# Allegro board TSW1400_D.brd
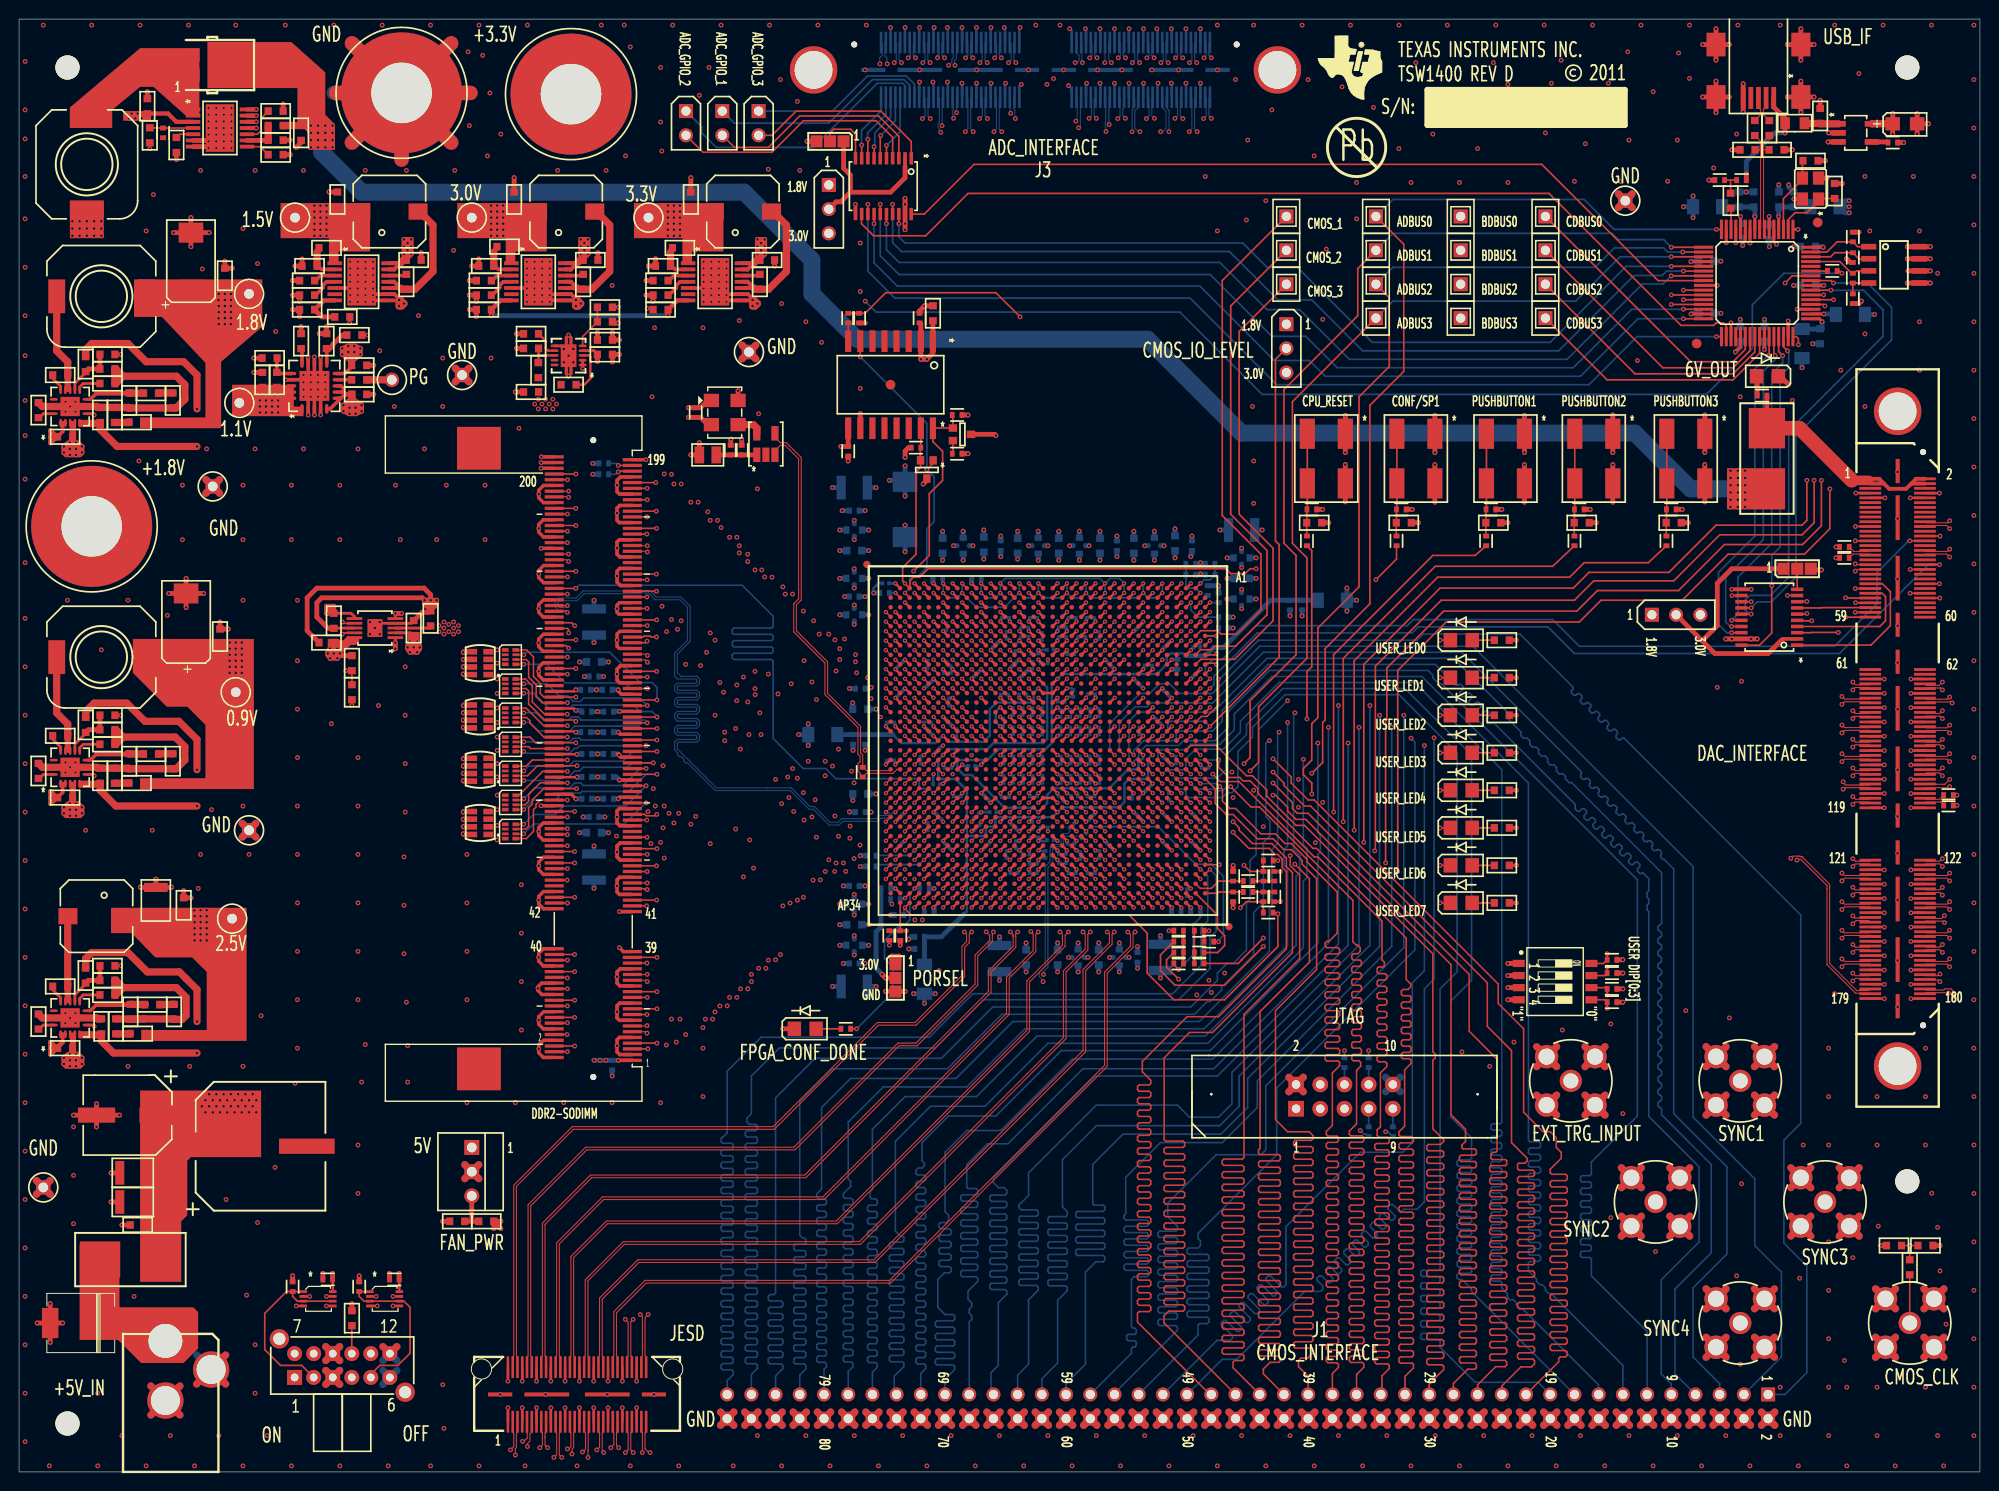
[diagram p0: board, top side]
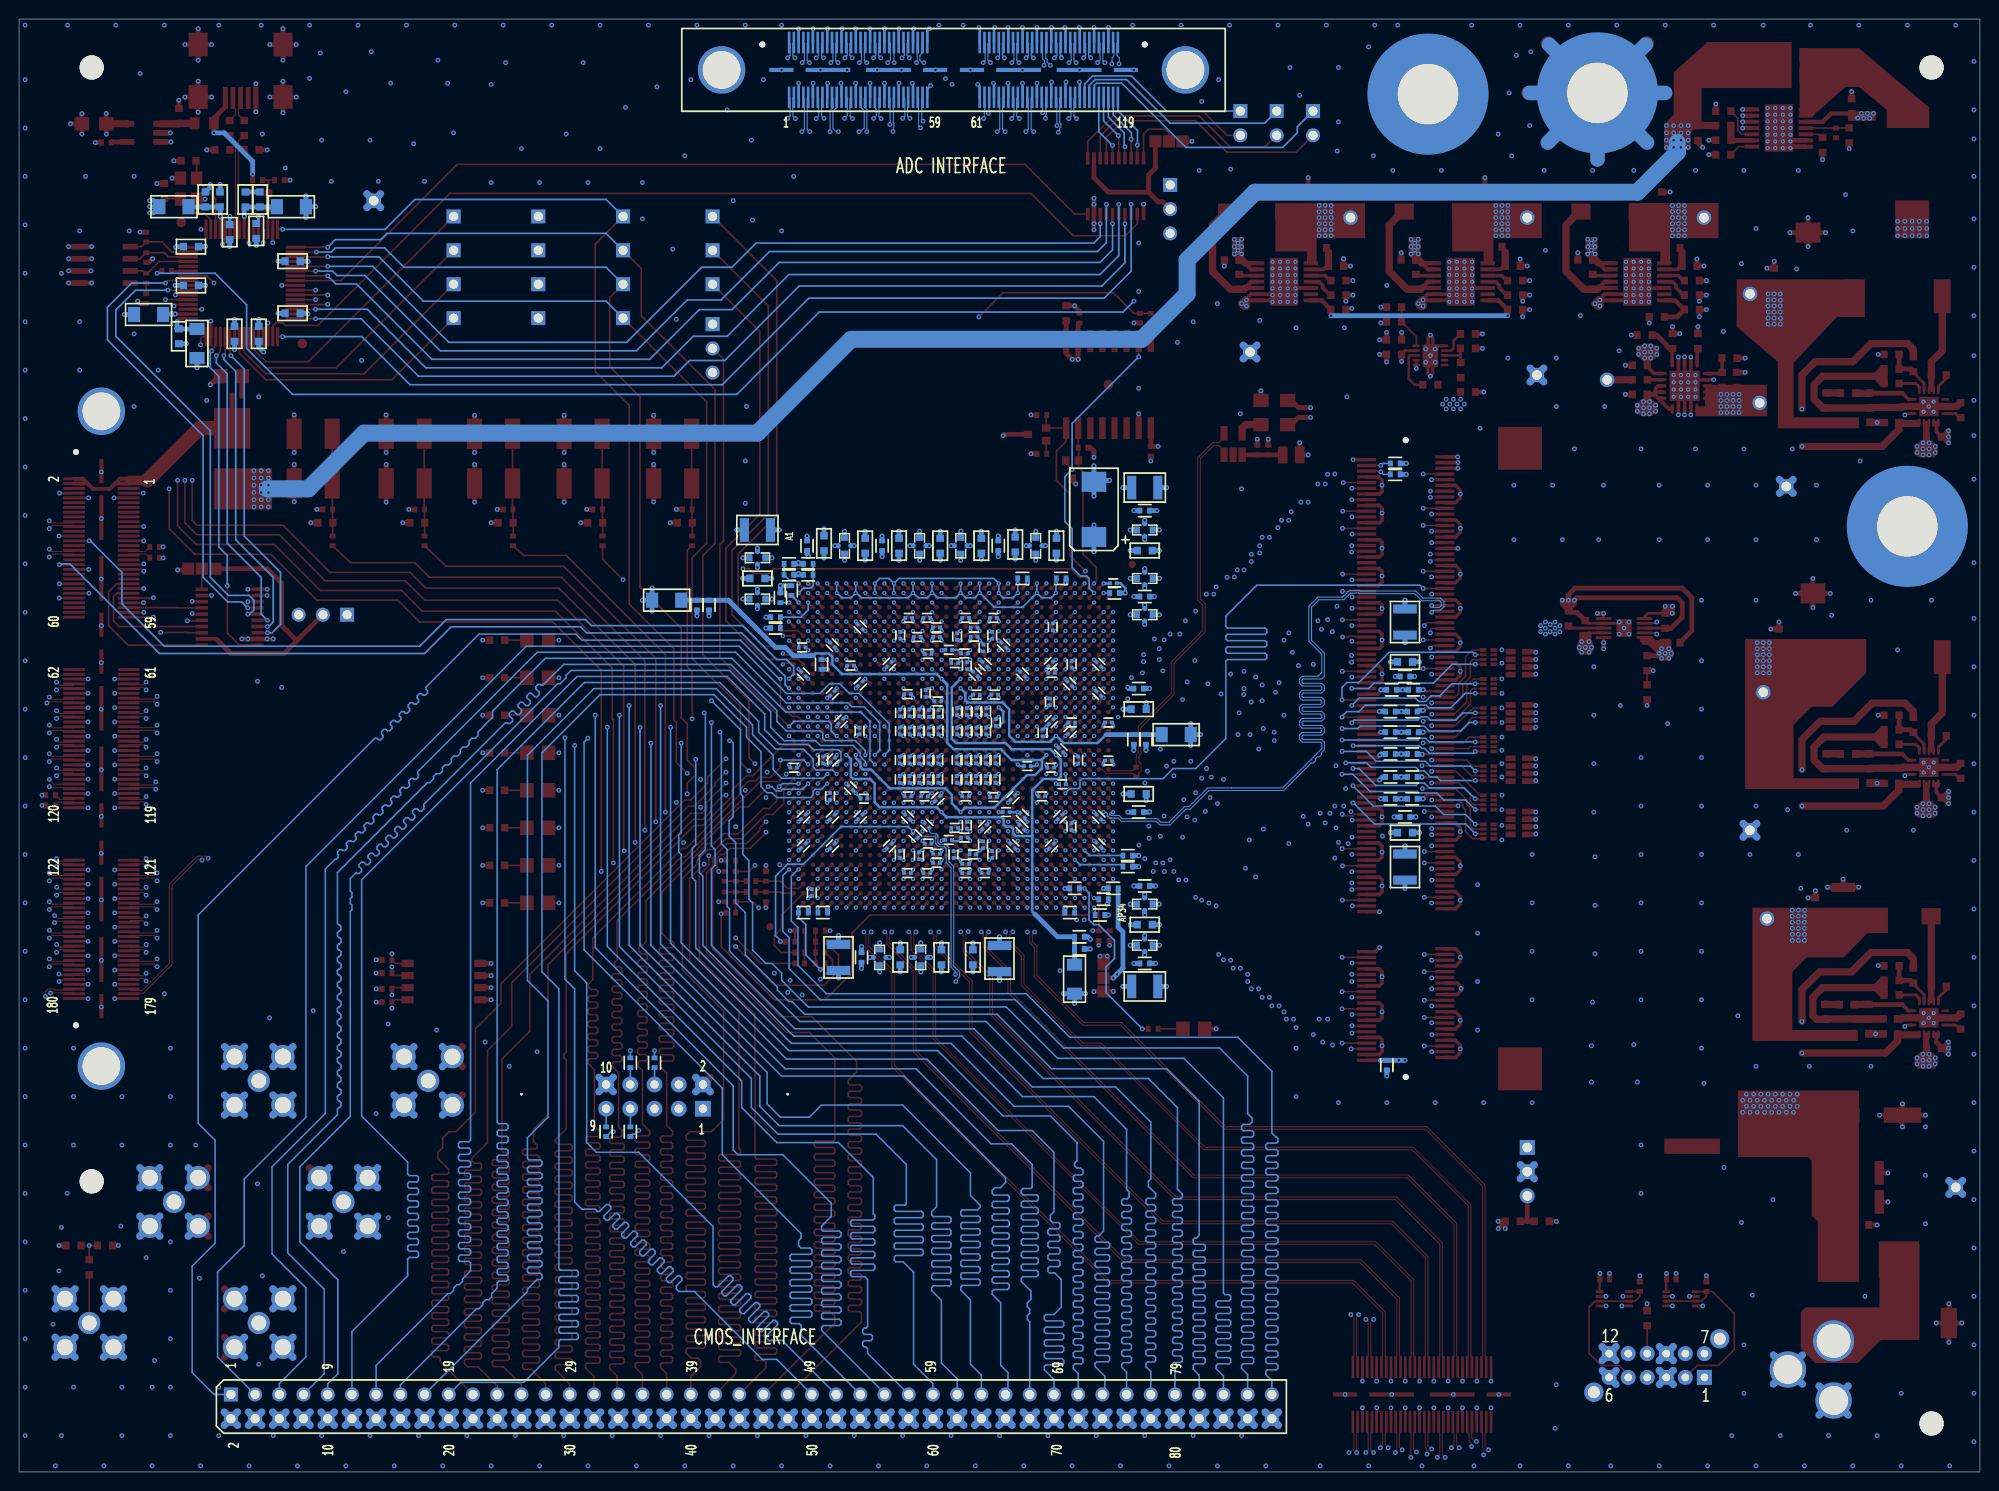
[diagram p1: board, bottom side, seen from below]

Outline 205.74 x 152.4 mm; copper layers: TOP, L2-GND1, L3-SIG1, L4-SIG2, L5-GND2, L6-PWR1, L7-PWR2, L8-GND3, L9-SIG3, L10-SIG4, L11-GND4, BOTTOM. Coordinates in mm from the lower left corner of the outline.
Outline path: 0,152.4 205.74,152.4 205.74,0 0,0 0,152.4

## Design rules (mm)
net group DIFFPAIR2: nets GXB_RX2M GXB_RX2P
net group DIFFPAIR11: nets GXB_TX2M GXB_TX2P
net group DIFFPAIR20: nets CLK_OSCN CLK_OSCP
net group DIFFPAIR26: nets DS5N DS5P
net group DIFFPAIR28: nets DS3N DS3P
net group DIFFPAIR31: nets DBCLKN DBCLKP
net group DIFFPAIR32: nets DA15N DA15P
net group DIFFPAIR33: nets DA14N DA14P
net group DIFFPAIR34: nets DA13N DA13P
net group DIFFPAIR35: nets DA12N DA12P
net group DIFFPAIR36: nets DA11N DA11P
net group DIFFPAIR37: nets DA10N DA10P
net group DIFFPAIR38: nets DA9N DA9P
net group DIFFPAIR39: nets DA8N DA8P
net group DIFFPAIR40: nets DACLKN DACLKP
net group DIFFPAIR41: nets FPGA_CLKN FPGA_CLKP
net group DIFFPAIR42: nets DB8N DB8P
net group DIFFPAIR43: nets DB9N DB9P
net group DIFFPAIR44: nets DB10N DB10P
net group DIFFPAIR45: nets DB11N DB11P
net group DIFFPAIR46: nets DB12N DB12P
net group DIFFPAIR47: nets DB13N DB13P
net group DIFFPAIR48: nets DB14N DB14P
net group DIFFPAIR49: nets DB15N DB15P
net group DIFFPAIR50: nets DA7N DA7P
net group DIFFPAIR51: nets DA6N DA6P
net group DIFFPAIR52: nets DA5N DA5P
net group DIFFPAIR53: nets DA4N DA4P
net group DIFFPAIR54: nets DA3N DA3P
net group DIFFPAIR55: nets DA2N DA2P
net group DIFFPAIR56: nets DA1N DA1P
net group DIFFPAIR57: nets DA0N DA0P
net group DIFFPAIR58: nets OSTROBE_N OSTROBE_P
net group DIFFPAIR59: nets SYNCA_N SYNCA_P
net group DIFFPAIR60: nets ISTROBE_N ISTROBE_P
net group DIFFPAIR61: nets PARITY_N PARITY_P
net group DIFFPAIR62: nets DB0N DB0P
net group DIFFPAIR63: nets DB1N DB1P
net group DIFFPAIR64: nets DB2N DB2P
net group DIFFPAIR65: nets DB3N DB3P
net group DIFFPAIR66: nets DB4N DB4P
net group DIFFPAIR67: nets DB5N DB5P
net group DIFFPAIR68: nets DB6N DB6P
net group DIFFPAIR69: nets DB7N DB7P
net group DIFFPAIR71: nets INPUT10_M INPUT10_P
net group DIFFPAIR88: nets INPUT0_M INPUT0_P
net group DIFFPAIR89: nets INPUT1_M INPUT1_P
net group DIFFPAIR109: nets DM DP
net group DIFFPAIR110: nets N27224376 N27224380
net group DIFFPAIR111: nets DDR2_DQS7 DDR2_DQSN7
net group DIFFPAIR112: nets DDR2_DQS6 DDR2_DQSN6
net group DIFFPAIR113: nets DDR2_DQS1 DDR2_DQSN1
net group DIFFPAIR114: nets DDR2_DQS4 DDR2_DQSN4
net group DIFFPAIR115: nets DDR2_DQS0 DDR2_DQSN0
net group DIFFPAIR116: nets DDR2_DQS3 DDR2_DQSN3
net group DIFFPAIR117: nets DDR2_DQS2 DDR2_DQSN2
net group DIFFPAIR118: nets DDR2_DQS5 DDR2_DQSN5
net group DIFFPAIR119: nets DDR2_CLK_N1 DDR2_CLK_P1
net group DIFFPAIR120: nets FPGA_CLK2_N FPGA_CLK2_P
net group DIFFPAIR141: nets FPGACLK2N FPGACLK2P
net group DIFFPAIR142: nets FPGACLKN FPGACLKP
net group 100 OHM: nets CLK_GXB1_M CLK_GXB1_P CLK_GXB2_M CLK_GXB2_P CLK_GXB3_M CLK_GXB3_P CLK_GXB4_M CLK_GXB4_P DCLK_M DCLK_P FCLK_M FCLK_P GXB_RX0M GXB_RX0P GXB_RX1M GXB_RX1P GXB_RX3M GXB_RX3P GXB_RX4P GXB_RX5M GXB_RX5P GXB_RX6M GXB_RX6P GXB_RX7P GXB_TX0M GXB_TX0P GXB_TX1M GXB_TX1P GXB_TX3M GXB_TX3P GXB_TX4P GXB_TX5M GXB_TX5P GXB_TX6M GXB_TX6P GXB_TX7P INPUT2_P INPUT3_P INPUT4_M INPUT4_P INPUT5_M INPUT5_P INPUT6_M INPUT6_P INPUT7_M INPUT7_P INPUT8_M INPUT8_P INPUT9_M INPUT9_P INPUT11_M INPUT11_P INPUT12_P INPUT13_M INPUT13_P INPUT14_M INPUT14_P INPUT15_P INPUT16_M INPUT16_P INPUT17_M INPUT17_P INPUT18_P INPUT19_M INPUT19_P INPUT20_P INPUT21_P INPUT22_M INPUT22_P INPUT23_P INPUT24_M INPUT24_P INPUT25_P INPUT26_M INPUT26_P INPUT27_P INPUT28_P INPUT29_P INPUT30_M INPUT30_P INPUT31_P INPUT32_M INPUT32_P INPUT33_P INPUT34_M INPUT34_P N28765297
net group DIFFPAIR4: nets GXB_RX4M
net group DIFFPAIR6: nets GXB_RX7M
net group DIFFPAIR13: nets GXB_TX4M
net group DIFFPAIR16: nets GXB_TX7M
net group DIFFPAIR73: nets INPUT12_M
net group DIFFPAIR76: nets INPUT15_M
net group DIFFPAIR79: nets INPUT18_M
net group DIFFPAIR80: nets INPUT28_M
net group DIFFPAIR81: nets INPUT29_M
net group DIFFPAIR83: nets INPUT31_M
net group DIFFPAIR85: nets INPUT33_M
net group DIFFPAIR90: nets INPUT2_M
net group DIFFPAIR91: nets INPUT3_M
net group DIFFPAIR99: nets INPUT20_M
net group DIFFPAIR100: nets INPUT21_M
net group DIFFPAIR102: nets INPUT23_M
net group DIFFPAIR104: nets INPUT25_M
net group DIFFPAIR106: nets INPUT27_M

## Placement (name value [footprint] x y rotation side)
C1  0.1uF  [0603]  181.99 133.48 90 bottom
C2  4.7uF  [0603]  180.47 133.48 90 bottom
C3  10uF  [0603]  188.98 119.13 270 bottom
C4  100uF  [1206]  187.07 118.36 270 bottom
C5  0.1uF  [0603]  186.18 133.48 90 bottom
C6  4.7uF  [0603]  184.66 133.48 90 bottom
C7  100uF  [1206]  192.15 121.41 0 bottom
C8  10uF  [0603]  188.98 142.24 90 top
C9  4.7uF  [TANT_A]  197.87 141.41 0 top
C10  0.01uF  [0402]  196.6 139.45 0 top
C11  22pF  [0603]  181.36 138.68 180 top
C12  22pF  [0603]  184.4 138.68 0 top
C13  0.1uF  [0603]  180.59 119.38 90 bottom
C14  0.1uF  [0603]  187.71 128.52 180 bottom
C15  0.1uF  [0603]  180.85 130.18 270 bottom
C16  0.1uF  [0603]  177.04 121.54 0 bottom
C17  0.1uF  [0603]  177.04 127 0 bottom
C18  0.1uF  [0603]  187.71 124.46 180 bottom
C19  0.1uF  [0603]  183.13 119.38 90 bottom
C20  27pF  [0603]  190.5 134.37 90 top
C21  27pF  [0603]  187.96 137.54 0 top
C22  0.1uF  [0402]  61.72 82.04 180 bottom
C23  0.1uF  [0402]  61.85 79.76 180 bottom
C24  0.1uF  [0402]  61.85 77.6 180 bottom
C25  0.1uF  [0402]  61.85 75.31 180 bottom
C26  0.1uF  [0402]  61.85 72.9 180 bottom
C27  0.1uF  [0402]  61.85 70.61 180 bottom
C28  0.1uF  [0402]  59.44 82.04 0 bottom
C29  0.1uF  [0402]  59.44 77.6 0 bottom
C30  0.1uF  [0402]  59.56 79.76 0 bottom
C31  0.1uF  [0402]  59.56 75.31 0 bottom
C32  0.1uF  [0402]  59.56 72.9 0 bottom
C33  0.1uF  [0402]  59.56 70.61 0 bottom
C34  0.1uF  [0402]  62.23 42.67 270 bottom
C35  100uF  [1210]  60.33 63.45 270 bottom
C36  4.7uF  [0603]  60.33 67.06 0 bottom
C37  2.2uF  [0603]  60.33 84.96 180 bottom
C38  1uF  [0402]  60.33 68.71 0 bottom
C39  0.47uF  [0402]  60.33 83.44 180 bottom
C40  1uF  [0402]  75.82 107.19 90 top
C41  0.1uF  [0402]  74.68 107.19 90 top
C45  0.1uF  [0402]  70.99 111.12 270 top
C46  0.1uF  [0603]  198.37 21.46 90 top
C47  1uF  [0603]  25.53 114.55 270 top
C48  1uF  [0603]  35.69 113.03 180 top
C49  0.1uF  [0603]  29.59 118.62 270 top
C50  1uF  [0603]  35.69 116.08 180 top
C51  0.1uF  [0603]  4.32 77.22 0 top
C52  10uF  [0603]  41.4 127.13 0 top
C53  0.1uF  [0603]  21.08 87.63 270 top
C54  470uF  [TANT_E]  17.53 89.15 90 top
C55  10uF  [0603]  4.83 70.74 180 top
C56  10uF  [0603]  8.51 73.03 90 top
C57  330pF  [0603]  11.56 74.55 270 top
C58  0.018uF  [0603]  9.27 76.33 0 top
C59  0.1uF  [0603]  40.64 124.84 90 top
C60  1uF  [0603]  30.23 124.97 0 top
C61  0.1uF  [0603]  30.23 123.44 0 top
C62  22uF  [0603]  33.4 133.48 90 top
C63  1500pF  [0603]  16.13 74.55 270 top
C64  0.1uF  [0603]  4.32 115.06 0 top
C65  0.1uF  [0603]  21.59 125.48 270 top
C66  470uF  [TANT_E]  18.03 127 90 top
C67  10uF  [0603]  4.83 108.58 180 top
C68  10uF  [0603]  8.51 110.87 90 top
C69  330pF  [0603]  11.56 112.39 270 top
C70  0.018uF  [0603]  9.27 114.17 0 top
C71  22uF  [0603]  43.18 89.53 90 top
C72  22uF  [0603]  41.4 88.52 90 top
C73  4.7uF  [0603]  32.26 87 180 top
C74  1500pF  [0603]  16.13 112.39 270 top
C75  0.1uF  [0603]  33.02 89.28 90 top
C76  1uF  [0603]  12.45 25.91 0 top
C77  47uF  [CAP_SMD_8MM]  11.23 37.43 270 top
C78  680uF  [CAP_SMD_12_5MM]  25.34 34.16 90 top
C79  10uF  [0603]  78.49 127.13 0 top
C80  10uF  [1210]  11.94 28.32 180 top
C81  10uF  [1210]  11.94 31.37 180 top
C82  0.1uF  [0603]  77.72 124.84 90 top
C83  1uF  [0603]  67.31 124.97 0 top
C84  0.1uF  [0603]  67.31 123.44 0 top
C85  22uF  [0603]  70.48 133.48 90 top
C86  0.1uF  [0603]  4.32 50.93 0 top
C87  0.1uF  [0603]  17.27 59.44 270 top
C88  100uF  [1210]  14.35 59.94 90 top
C90  1200pF  [0603]  11.68 48.26 270 top
C91  0.018uF  [0603]  9.27 50.04 0 top
C92  22uF  [0603]  4.83 44.45 180 top
C93  .022uF  [0603]  16.26 48.26 270 top
C94  2.2uF  [0603]  95.89 121.54 90 top
C95  0.1uF  [0402]  94.49 121.03 90 top
C96  10uF  [0603]  59.94 127.13 0 top
C97  0.1uF  [0603]  59.18 124.84 90 top
C98  1uF  [0603]  48.77 124.97 0 top
C99  0.1uF  [0603]  48.77 123.44 0 top
C100  22uF  [0603]  51.94 133.48 90 top
C101  22uF  [1210]  102.87 53.85 270 bottom
C102  10uF  [0603]  105.66 53.98 270 bottom
C103  0.1uF  [0201]  111.33 64.64 90 bottom
C104  0.1uF  [0201]  106.43 62.81 180 bottom
C105  0.1uF  [0201]  104.39 62.81 180 bottom
C106  0.1uF  [0201]  112.52 62.81 0 bottom
C107  0.1uF  [0201]  110.49 62.81 0 bottom
C108  0.1uF  [0201]  107.7 64.77 90 bottom
C109  4.7uF  [0603]  109.09 97.16 270 bottom
C110  0.1uF  [0201]  109.47 63.88 0 bottom
C111  0.1uF  [0201]  106.43 63.78 180 bottom
C112  0.1uF  [0201]  105.54 88.57 0 bottom
C113  0.1uF  [0201]  109.47 88.6 0 bottom
C114  22uF  [1210]  60.33 89.15 90 bottom
C115  0.47uF  [0402]  88.27 69.22 180 bottom
C116  0.47uF  [0402]  88.27 82.17 180 bottom
C117  10uF  [0603]  88.27 71.12 180 bottom
C118  0.1uF  [0201]  92.46 65.79 45 bottom
C119  0.1uF  [0201]  91.44 74.63 180 bottom
C120  0.1uF  [0201]  96.52 68.71 135 bottom
C121  0.1uF  [0201]  96.27 72.14 0 bottom
C122  0.1uF  [0201]  94.61 74.68 90 bottom
C123  0.1uF  [0201]  92.46 68.71 45 bottom
C124  10uF  [0603]  108.97 53.98 270 bottom
C125  0.1uF  [0201]  120.4 65.66 135 bottom
C126  0.1uF  [0201]  103.5 70.79 180 bottom
C127  0.1uF  [0201]  110.74 70.87 180 bottom
C128  0.1uF  [0201]  113.31 79.63 270 bottom
C129  0.1uF  [0201]  118.49 84.58 0 bottom
C130  0.1uF  [0201]  106.43 70.87 0 bottom
C131  0.1uF  [0201]  95.3 84.71 90 bottom
C132  0.1uF  [0201]  120.4 86.74 225 bottom
C133  0.1uF  [0201]  103.25 78.61 270 bottom
C134  2.2uF  [0603]  88.27 80.01 180 bottom
C135  0.1uF  [0201]  109.35 70.64 315 bottom
C136  0.1uF  [0201]  119.51 78.74 135 bottom
C137  0.1uF  [0201]  118.49 71.75 45 bottom
C138  0.1uF  [0201]  120.4 81.66 135 bottom
C139  10uF  [0603]  104.78 97.16 90 bottom
C140  0.1uF  [0201]  123.44 83.69 225 bottom
C141  0.1uF  [0201]  112.47 70.87 180 bottom
C143  0.1uF  [0201]  102.18 69.22 0 bottom
C144  330uF  [TANT_D]  92.96 100.97 90 bottom
C145  100uF  [1210]  87.63 103.25 180 bottom
C146  100uF  [1210]  128.27 98.81 0 bottom
C147  100uF  [1210]  87.63 50.93 180 bottom
C148  100uF  [1210]  119.76 53.98 270 bottom
C149  10uF  [0603]  87.63 96.65 180 bottom
C150  10uF  [0603]  87.63 57.4 180 bottom
C151  10uF  [0603]  96.9 97.16 90 bottom
C152  10uF  [0603]  101.22 97.28 90 bottom
C153  10uF  [0603]  113.41 97.16 90 bottom
C154  10uF  [0603]  116.97 97.16 90 bottom
C155  10uF  [0603]  121.28 97.41 90 bottom
C156  2.2uF  [0603]  113.28 53.98 270 bottom
C157  0.1uF  [0201]  120.37 74.68 135 bottom
C158  0.1uF  [0201]  104.27 77.72 270 bottom
C159  0.1uF  [0201]  111.3 79.63 270 bottom
C160  0.1uF  [0201]  106.3 84.58 90 bottom
C161  0.1uF  [0201]  106.3 77.72 270 bottom
C162  0.1uF  [0201]  122.56 60.76 90 bottom
C163  10uF  [0603]  128.27 93.73 0 bottom
C164  0.1uF  [0201]  105.28 79.76 90 bottom
C165  0.1uF  [0201]  106.55 66.55 180 bottom
C166  0.1uF  [C-0603_X2Y]  87.63 59.56 0 bottom
C167  0.1uF  [C-0603_X2Y]  87.63 55.24 0 bottom
C168  0.1uF  [C-0603_X2Y]  87.63 98.81 180 bottom
C169  0.1uF  [C-0603_X2Y]  115.44 53.98 270 bottom
C170  0.1uF  [C-0603_X2Y]  106.93 97.16 270 bottom
C171  0.22uF  [C-0603_X2Y]  111.25 97.16 270 bottom
C172  0.22uF  [C-0603_X2Y]  128.27 91.57 180 bottom
C173  10nF  [C-0603_X2Y]  87.63 93.73 180 bottom
C174  10nF  [C-0603_X2Y]  128.27 95.89 0 bottom
C175  10nF  [C-0603_X2Y]  99.06 97.16 270 bottom
C176  10nF  [C-0603_X2Y]  119.13 97.16 90 bottom
C177  10nF  [C-0603_X2Y]  111.12 53.98 90 bottom
C178  10nF  [C-0603_X2Y]  87.63 89.92 180 bottom
C179  22nF  [0201]  104.32 72.64 90 bottom
C180  22nF  [0201]  104.27 79.76 90 bottom
C181  22nF  [0201]  109.3 72.64 90 bottom
C182  22nF  [0201]  99.95 74.04 0 bottom
C183  22nF  [0201]  111.3 77.72 90 bottom
C184  22nF  [0201]  95.3 78.61 180 bottom
C185  22nF  [0201]  112.29 77.72 270 bottom
C186  0.1uF  [0201]  123.44 65.68 135 bottom
C187  22nF  [0201]  111.3 72.64 90 bottom
C188  22nF  [0201]  107.37 74.68 270 bottom
C189  0.1uF  [0201]  90.93 93.22 180 bottom
C190  22nF  [0201]  108.2 86.23 180 bottom
C191  22nF  [0201]  100.46 68.86 45 bottom
C192  22nF  [0201]  111.3 74.68 90 bottom
C193  22nF  [0201]  105.28 77.72 270 bottom
C194  22nF  [0201]  105.33 74.68 270 bottom
C195  22nF  [0201]  112.32 72.64 270 bottom
C196  22nF  [0201]  110.31 74.68 270 bottom
C197  0.47uF  [0402]  87.63 100.84 180 bottom
C198  0.47uF  [0402]  87.63 91.82 180 bottom
C199  1uF  [0402]  87.63 61.47 180 bottom
C200  1uF  [0402]  87.63 53.34 180 bottom
C201  1uF  [0402]  103 97.16 90 bottom
C202  1uF  [0402]  115.19 97.16 90 bottom
C203  1uF  [0402]  117.35 53.98 270 bottom
C204  1uF  [0402]  123.06 97.16 90 bottom
C205  22nF  [0201]  110.29 77.72 270 bottom
C206  22nF  [0201]  112.32 74.68 270 bottom
C207  22nF  [0201]  108.2 66.29 180 bottom
C208  22nF  [0201]  110.29 79.55 270 bottom
C209  22nF  [0201]  107.37 72.64 270 bottom
C210  22nF  [0201]  106.35 72.64 90 bottom
C211  22nF  [0201]  104.6 65.79 270 bottom
C212  22nF  [0201]  97.49 73.86 0 bottom
C213  22nF  [0201]  106.35 74.68 90 bottom
C214  22nF  [0201]  107.57 84.84 0 bottom
C215  22nF  [0201]  106.3 79.76 90 bottom
C216  22nF  [0201]  105.33 72.64 270 bottom
C217  22nF  [0201]  106.3 67.82 90 bottom
C218  0.1uF  [0201]  97.41 83.82 180 bottom
C219  22nF  [0201]  97.59 80.77 90 bottom
C220  22nF  [0201]  104.32 74.68 90 bottom
C221  22nF  [0201]  112.32 79.63 270 bottom
C222  22nF  [0201]  107.57 67.56 0 bottom
C223  22nF  [0201]  106.55 85.85 0 bottom
C224  0.1uF  [0201]  95.33 67.69 270 bottom
C225  22nF  [0201]  107.31 77.72 270 bottom
C226  22nF  [0201]  107.31 79.76 270 bottom
C227  0.1uF  [0402]  87 107.06 270 top
C228  22nF  [0201]  104.55 86.44 90 bottom
C229  22nF  [0201]  104.39 84.71 225 bottom
C230  22nF  [0201]  110.36 65.91 0 bottom
C231  22nF  [0201]  109.3 74.68 90 bottom
C232  22nF  [0201]  104.42 67.67 135 bottom
C233  0.1uF  [0201]  109.47 64.85 0 bottom
C234  0.1uF  [0201]  105.66 64.77 0 bottom
C235  0.1uF  [0201]  105.54 87.6 0 bottom
C236  0.1uF  [0201]  107.31 87.63 270 bottom
C237  0.1uF  [0201]  106.43 89.59 180 bottom
C238  0.1uF  [0201]  103.5 89.59 0 bottom
C239  0.1uF  [0201]  111.51 87.58 180 bottom
C240  0.1uF  [0201]  109.47 87.58 0 bottom
C241  0.1uF  [0201]  112.39 89.59 0 bottom
C242  0.1uF  [0201]  110.49 89.59 0 bottom
C243  0.1uF  [0201]  117.09 70.61 180 bottom
C244  0.1uF  [0201]  103.3 72.64 90 bottom
C245  0.1uF  [0201]  97.28 88.65 270 bottom
C246  0.1uF  [0201]  103.3 74.68 90 bottom
C247  0.1uF  [0201]  98.42 70.87 0 bottom
C248  0.1uF  [0201]  117.55 77.72 270 bottom
C249  0.1uF  [0201]  112.52 81.58 0 bottom
C250  0.1uF  [0201]  113.31 77.72 270 bottom
C251  0.1uF  [0201]  123.44 68.71 135 bottom
C252  0.1uF  [0201]  120.4 68.71 135 bottom
C253  0.1uF  [0201]  113.33 74.68 270 bottom
C254  0.1uF  [0201]  113.33 72.64 270 bottom
C255  0.1uF  [0201]  121.36 74.68 90 bottom
C257  0.1uF  [0201]  120.65 70.87 270 bottom
C258  0.1uF  [0201]  123.57 86.49 180 bottom
C259  0.1uF  [0201]  124.46 73.86 0 bottom
C260  22nF  [0201]  110.36 85.8 0 bottom
C261  22nF  [0201]  109.27 79.55 90 bottom
C262  22nF  [0201]  109.27 77.72 90 bottom
C263  22nF  [0201]  110.31 72.64 270 bottom
C264  0.1uF  [0402]  202.44 69.91 180 top
C265  0.1uF  [0201]  97.41 65.66 135 bottom
C266  0.1uF  [0201]  100.51 67.61 225 bottom
C267  0.1uF  [0201]  101.47 70.74 315 bottom
C268  0.1uF  [0201]  97.43 78.71 135 bottom
C269  0.1uF  [0201]  95.45 77.67 315 bottom
C270  0.1uF  [0201]  95.5 82.68 45 bottom
C271  0.1uF  [0201]  91.44 78.61 180 bottom
C272  0.1uF  [0201]  92.46 81.66 45 bottom
C273  0.1uF  [0201]  92.46 84.71 45 bottom
C274  0.1uF  [0201]  97.49 84.76 135 bottom
C275  0.1uF  [0201]  100.46 83.69 225 bottom
C276  0.1uF  [0201]  102.44 86.74 225 bottom
C277  0.1uF  [0201]  117.47 88.65 225 bottom
C278  0.1uF  [0201]  109.35 80.82 180 bottom
C279  0.1uF  [0201]  114.43 84.71 135 bottom
C280  0.1uF  [0201]  117.48 82.68 135 bottom
C281  0.1uF  [0201]  114.43 65.66 135 bottom
C282  0.1uF  [0201]  105.41 83.69 225 bottom
C283  0.1uF  [0201]  103.38 81.53 0 bottom
C284  0.1uF  [0201]  110.62 81.66 90 bottom
C285  0.1uF  [0201]  101.47 65.66 45 bottom
C286  0.1uF  [0201]  105.28 81.53 0 bottom
C287  0.1uF  [0201]  112.52 68.71 45 bottom
C288  0.1uF  [0201]  98.35 77.52 270 bottom
C289  0.1uF  [0201]  117.47 68.71 135 bottom
C290  0.1uF  [0201]  96.42 75.72 225 bottom
C291  0.1uF  [0402]  202.44 70.99 180 top
C292  0.1uF  [0402]  191.52 97.03 0 top
C293  0.1uF  [0402]  191.52 95.89 0 top
C294  1uF  [0603]  13.46 143.26 270 top
C295  10uF  [0603]  16.51 139.19 270 top
C296  .027uF  [0603]  29.59 140.46 270 top
C328  2.2uF  [0402]  87.5 76.83 270 bottom
C329  2.2uF  [0402]  134.62 90.93 270 bottom
C330  2.2uF  [0402]  94.49 54.86 180 bottom
C331  22uF  [0402]  88.77 76.83 270 bottom
C332  22uF  [0402]  133.35 90.93 270 bottom
C333  22uF  [0402]  94.49 56.13 180 bottom
C334  1uF  [0603]  61.47 118.75 180 top
C335  1uF  [0603]  61.47 117.22 180 top
C336  10uF  [0603]  53.72 113.28 180 top
C337  270pF  [0603]  53.72 119.38 180 top
C338  0.1uF  [0603]  145.29 99.57 0 top
C339  0.1uF  [0603]  154.69 99.57 0 top
C340  0.1uF  [0603]  163.96 99.57 0 top
C341  0.1uF  [0603]  173.61 99.57 0 top
C342  0.1uF  [0603]  135.89 99.57 0 top
C349  0.1uF  [0402]  39.37 20.19 180 top
C350  0.1uF  [0402]  32.38 20.19 180 top
C351  10pF  [0402]  94.11 107.44 180 top
C352  10pF  [0402]  98.42 106.81 0 top
C353  10pF  [0402]  98.42 110.87 0 top
C354  10pF  [0402]  88.14 121.03 270 top
C355  4.7pF  [0603]  8.64 46.74 90 top
CN1  0.1uF x4  [CA-AVE-0603-8]  48.39 84.84 90 top
CN4  0.1uF x4  [CA-AVE-0603-8]  48.39 79.25 90 top
CN7  0.1uF x4  [CA-AVE-0603-8]  48.39 73.66 90 top
CN10  0.1uF x4  [CA-AVE-0603-8]  48.39 68.07 90 top
D1  GREEN  [LED_0805]  82.49 46.48 180 top
D2  GREEN  [LED_0805]  151.32 87.25 180 top
D3  GREEN  [LED_0805]  151.32 83.31 180 top
D4  GREEN  [LED_0805]  151.32 79.38 180 top
D5  GREEN  [LED_0805]  151.32 75.44 180 top
D6  GREEN  [LED_0805]  151.32 71.5 180 top
D7  GREEN  [LED_0805]  151.32 67.56 180 top
D8  GREEN  [LED_0805]  151.32 63.63 180 top
D9  GREEN  [LED_0805]  151.32 59.69 180 top
D10  LED GREEN  [LED_0805]  183.45 114.94 0 top
D11  SS3P6L, 3A, 60V  [DIODE_SM_SS3P6L]  22.12 147.57 180 top
D14  B540C-13-F  [DO-214AB_RECTRON]  6.48 15.62 180 top
DN1  BAT54CW  [SOT_323]  95.25 105.16 180 top
DN2  BAT54CW  [SOT_323]  98.93 108.84 270 top
F1  4 AMP FUSE  [FUSE_SM_NANO]  11.68 22.28 0 top
F2  2 AMP FUSE  [FUSE_SM_NANO]  183.39 106.3 90 top
FB1  68 OHM @ 100MHz  [1206]  177.16 132.72 0 bottom
FB2  68 OHM @ 100MHz  [1206]  189.48 132.72 180 bottom
FB4  68 ohm @ 100MHz  [1206]  95 51.69 90 bottom
FB5  68 ohm @ 100MHz  [1206]  137.79 91.44 180 bottom
FB6  68 ohm @ 100MHz  [1206]  84.33 77.34 0 bottom
J1  SSQ-144-01-G-D  [HDR_THVT_2X44_100_F]  183.51 8.13 90 bottom
J2  QSH-030-01-L-D-A  [CON_SMVT_60POS_QSH_SAMTEC]  58.55 8.13 0 top
J3  QSH-060-01-L-D-A-RT1  [CON_SMVT_120POS_QSH_SAMTEC_RT1]  107.7 147.07 180 bottom
J4  QSH-090-01-L-D-A-RT1  [CON_SMVT_180POS_QSH_SAMTEC_RT1]  199.77 107.02 270 top
J5  USB_MINI_AB_MNE20-5G5P10  [CON_SMRT_USBMNE20_F]  182.5 147.57 270 top
J6  -  [SOCKET-SO-DIMM200]  60.25 74.83 90 top
J7  SMB_THVT_REC  [SMA_THVT_312X312]  198.37 15.62 180 top
J8  BANANA_JACK_RED  [CON_THVT_BANANA_JACK_250DIA]  7.62 99.19 0 top
J9  BANANA_JACK_BLK  [CON_THVT_BANANA_JACK_250DIA]  40.13 144.65 0 top
J10  BANANA_JACK_RED  [CON_THVT_BANANA_JACK_250DIA]  57.91 144.53 0 top
J11  SMB_THVT_REC  [SMA_THVT_312X312]  162.81 41.02 0 top
J12  CONN JACK PWR  [CON_THRT_POWERJACK_RAPC722]  15.35 10.62 0 top
J13  102153-1  [CON_THVT_2X5_100_M]  133.99 38.1 90 top
J14  SMB_THVT_REC  [SMA_THVT_312X312]  180.59 41.02 0 top
J15  SMB_THVT_REC  [SMA_THVT_312X312]  171.7 28.32 0 top
J16  SMB_THVT_REC  [SMA_THVT_312X312]  189.48 28.32 0 top
J17  SMB_THVT_REC  [SMA_THVT_312X312]  180.59 15.62 0 top
J18  22-11-2032  [HDR_THVT_1X3_100_M_KEYED]  47.5 34.04 0 top
JP3  HEADER_1x3_100_430L  [HDR_THVT_1X3_100_M]  84.96 135 0 top
JP4  HEADER_1x3_100_430L  [HDR_THVT_1X3_100_M]  171.32 89.92 90 top
JP5  JUMPER_1X2_100  [HDR_THVT_1X2_100_M]  77.6 142.75 0 top
JP6  JUMPER_1X2_100  [HDR_THVT_1X2_100_M]  73.79 142.75 0 top
JP7  JUMPER_1X2_100  [HDR_THVT_1X2_100_M]  69.98 142.75 0 top
JP8  HEADER_1x3_100_430L  [HDR_THVT_1X3_100_M]  132.97 120.4 0 top
L3  1K  @ 100MHZ  [0805]  186.31 141.48 0 top
L4  1.5A/330  [IND_0805]  72.26 106.68 0 top
L6  1.5uH  [IND_SM_MSS1048]  8.64 85.47 0 top
L7  2.2uH  [IND_SM_7447789002]  38.86 132.21 90 top
L8  1.5uH  [IND_SM_MSS1048]  8.64 123.32 0 top
L9  2.2uH  [IND_SM_7447789002]  75.95 132.21 90 top
L10  2.2uH  [IND_SM_7447789002]  8.13 58.29 270 top
L11  2.2uH  [IND_SM_7447789002]  57.4 132.21 90 top
L12  10uH  [IND_SM_MSS1048]  7.11 137.16 90 top
NOREF  -  [unnamed]  198.12 30.48 0 top
NOREF#2  -  [unnamed]  5.08 5.08 0 top
NOREF#3  -  [#2]  203.2 0 90 top
NOREF#4  -  [unnamed]  198.12 147.32 0 top
NOREF#5  -  [#2]  745.11 93.73 0 top
NOREF#6  -  [#2]  0 152.4 0 top
NOREF#7  -  [#2]  138.3 137.67 0 top
NOREF#8  -  [#2]  -93.85 -83.95 0 top
NOREF#9  -  [#2]  135.99 146.08 0 top
NOREF#10  -  [#2]  -24.13 15.24 0 top
NOREF#11  -  [unnamed]  5.08 147.32 0 top
NOREF#12  -  [#2]  140.91 142.18 0 top
NOREF#13  -  [#2]  109.69 128.56 0 top
R1  10  [0603]  183.64 140.97 270 top
R2  10  [0603]  182.12 140.97 270 top
R3  1K  [0603]  179.58 133.35 90 top
R4  12K  [0603]  183.64 130.05 270 bottom
R5  10K  [0402]  192.41 129.54 270 top
R6  10K  [0402]  192.41 127.38 90 top
R7  10K  [0402]  192.41 123.06 90 top
R8  2.2K  [0402]  192.41 125.22 270 top
R9  10K  [0402]  61.34 104.65 0 bottom
R10  10K  [0402]  61.34 105.79 0 bottom
R15  100  [0603]  196.72 23.75 0 top
R16  100  [0603]  200.03 23.75 0 top
R17  50  [0402]  89.41 63.5 0 bottom
R18  50  [0402]  89.41 64.64 0 bottom
R19  10K  [0603]  27.05 114.55 270 top
R20  100K  [0603]  35.69 114.55 180 top
R21  26.7K  [0603]  26.29 116.84 180 top
R22  10K  [0603]  32.26 118.62 270 top
R23  100K  [0603]  2.03 73.53 270 top
R24  13.3K  [0603]  12.32 72.26 0 top
R25  10K  [0603]  30.48 126.49 0 top
R26  10K  [0603]  32.26 128.4 0 top
R27  2.49K  [0603]  13.84 75.31 0 top
R28  78.7K  [0603]  10.03 73.03 90 top
R29  196K  [0603]  6.99 78.36 270 top
R30  56.2K  [0603]  9.27 77.85 0 top
R31  100K  [0603]  2.03 111.38 270 top
R32  13K  [0603]  12.32 110.11 0 top
R33  196K  [0603]  6.99 116.2 270 top
R34  2.49K  [0603]  13.84 113.16 0 top
R35  10.2K  [0603]  10.03 110.87 90 top
R36  56.2K  [0603]  9.27 115.7 0 top
R37  10K  [0603]  67.56 126.49 0 top
R38  34K  [0603]  69.34 128.4 0 top
R39  100K  [0603]  2.03 47.24 270 top
R40  21.5K  [0603]  12.45 45.97 0 top
R41  1.54K  [0603]  13.97 49.02 0 top
R42  10K  [0603]  10.16 46.74 90 top
R43  200K  [0603]  6.99 52.07 270 top
R44  57.6K  [0603]  9.27 51.56 0 top
R45  10K  [0402]  178.44 135.51 180 top
R46  4.7K  [0402]  180.72 135.51 180 top
R47  10K  [0603]  49.02 126.49 0 top
R48  30.1K  [0603]  50.93 128.52 0 top
R49  680  [0402]  95 61.21 180 bottom
R50  10K  [0402]  91.95 60.07 0 bottom
R51  10K  [0402]  92.33 58.42 0 bottom
R52  1K  [0402]  127.38 62.48 90 top
R53  10K  [0402]  127.38 60.33 90 top
R54  100  [0201]  103.63 87.76 270 bottom
R55  1K  [0402]  123.44 58.67 0 bottom
R56  100  [0201]  103.63 64.77 270 bottom
R57  0  [0402]  121.67 56.77 0 top
R58  0  [0402]  130.56 62.48 270 top
R59  0  [0402]  123.83 56.77 180 top
R60  0  [0402]  130.56 60.33 90 top
R61  0  [0402]  121.67 55.63 180 top
R62  0  [0402]  131.7 62.48 90 top
R63  0  [0402]  123.83 53.34 0 top
R64  0  [0402]  131.7 60.33 270 top
R65  1K  [0402]  182.88 112.9 0 top
R66  0  [0402]  190.25 125.98 0 top
R67  0  [0402]  86.74 46.48 0 top
R68  165  [0603]  155.57 87.25 180 top
R69  165  [0603]  155.57 83.31 180 top
R70  165  [0603]  155.57 79.38 180 top
R71  165  [0603]  155.57 75.44 180 top
R72  165  [0603]  155.57 67.56 180 top
R73  165  [0603]  155.57 71.5 180 top
R74  165  [0603]  155.57 63.63 180 top
R75  165  [0603]  155.57 59.69 180 top
R76  100  [0402]  88.52 73.41 270 top
R77  4.75K  [0402]  35.69 19.43 270 top
R79  4.75K  [0402]  28.7 19.43 270 top
R80  1K  [0402]  167.13 53.72 180 top
R81  1K  [0402]  167.13 52.32 180 top
R82  1K  [0402]  167.13 50.67 180 top
R83  1K  [0402]  167.13 49.28 180 top
R84  1K  [0402]  145.03 100.97 180 top
R85  1K  [0402]  154.43 100.97 180 top
R86  1K  [0402]  163.7 100.97 180 top
R87  1K  [0402]  173.35 100.97 180 top
R88  1K  [0402]  135.64 100.97 180 top
R89  0  [0402]  125.86 91.69 270 bottom
R90  0  [0402]  124.71 92.46 270 bottom
R91  10K  [0402]  96.39 93.73 180 bottom
R92  10K  [0402]  100.46 93.73 180 bottom
R93  2K  [0402]  121.41 58.67 180 bottom
R94  2K  [0402]  95.5 58.67 0 bottom
R95  0  [0402]  121.54 84.71 270 bottom
R96  10K  [0603]  57.66 114.05 0 top
R97  3.57K  [0603]  54.48 115.57 270 top
R98  1.27K  [0603]  53.72 117.86 0 top
R99  0  [0402]  144.53 97.66 90 top
R100  0  [0402]  153.92 97.66 90 top
R101  0  [0402]  163.19 97.66 90 top
R102  0  [0402]  172.85 97.66 90 top
R103  1K  [0402]  135.13 97.66 90 top
R104  100  [0201]  113.33 64.77 90 bottom
R105  100  [0201]  113.28 87.76 90 bottom
R113  10K  [0603]  30.23 121.92 180 top
R114  10K  [0603]  48.77 121.92 180 top
R115  0  [0603]  67.31 121.92 180 top
R116  0  [0603]  45.97 26.29 0 top
R117  0  [0603]  9.27 79.38 0 top
R118  0  [0603]  34.92 81.79 270 top
R119  0  [0603]  9.27 117.22 0 top
R120  4.75K  [0603]  34.92 84.84 270 top
R121  0  [0603]  33.91 121.16 0 top
R122  0  [0603]  35.18 119.25 0 top
R123  0  [0603]  9.27 53.09 0 top
R124  0  [0603]  61.47 122.17 0 top
R125  10K  [0603]  61.47 120.65 180 top
R126  0  [0402]  121.67 54.48 180 top
R127  0  [0402]  124.84 55.63 0 top
R128  0  [0402]  131.06 58.67 0 top
R129  0  [0402]  144.15 35.69 90 bottom
R130  0  [0402]  141.6 35.69 90 bottom
R131  0  [0402]  141.6 42.93 270 bottom
R132  0  [0402]  139.06 42.93 270 bottom
R133  10K  [0402]  92.46 56.26 270 top
R134  24.9  [0402]  87 121.03 270 top
R135  0  [0201]  111.71 66.75 44.8 bottom
R136  0  [0201]  110.49 67.82 45 bottom
R137  0  [0402]  122.94 94.11 180 bottom
R138  0  [0402]  122.94 95.25 0 bottom
R139  0  [0402]  126.36 89.66 0 bottom
R140  0  [0402]  126.36 88.52 180 bottom
R141  0  [0402]  124.97 94.11 0 bottom
R142  0  [0402]  124.97 95.25 180 bottom
R143  0  [0402]  90.81 92.2 0 bottom
R144  1K  [0402]  90.93 61.21 180 bottom
R145  38.3K  [0603]  26.92 141.22 180 top
R146  10K  [0603]  26.92 139.7 0 top
R147  10K  [0603]  26.92 138.18 0 top
R148  80.6K  [0603]  26.92 142.75 0 top
R149  0  [0402]  121.67 53.34 0 top
R150  0  [0402]  123.83 54.48 180 top
R151  0  [0402]  128.96 61.98 0 top
R152  0  [0402]  128.96 60.83 0 top
R153  0  [0402]  91.31 56.26 90 top
R154  0  [0603]  34.92 16.13 90 top
R155  0  [0603]  49.02 26.29 0 top
R156  0  [0402]  131.06 64.14 0 top
R157  0  [0603]  13.72 140.21 90 top
R158  1K  [0402]  15.11 140.46 270 top
RN8  56  [RA-VEX-0402-8]  51.56 85.47 270 top
RN9  56  [RA-VEX-0402-8]  51.56 82.42 270 top
RN12  56  [RA-VEX-0402-8]  51.56 79.38 270 top
RN13  56  [RA-VEX-0402-8]  51.56 76.33 270 top
RN18  56  [RA-VEX-0402-8]  51.56 73.28 270 top
RN19  56  [RA-VEX-0402-8]  51.56 70.23 270 top
RN24  56  [RA-VEX-0402-8]  51.56 67.18 270 top
SJP1  SOLDER JUMPER, 0603  [SMD_JUMPER_1X3]  85.09 139.57 180 top
SJP2  SOLDER JUMPER, 0603  [SMD_JUMPER_1X3]  186.56 94.74 0 top
SJP3  SOLDER JUMPER, 0603  [SMD_JUMPER_1X3]  91.95 51.82 270 top
SW1  TDA04H0SB1R  [SW-SMD-8]  161.16 51.44 270 top
SW2  KT11P3JM  [SW_SMVT_SPST_4]  146.56 106.3 270 top
SW3  KT11P3JM  [SW_SMVT_SPST_4]  155.96 106.3 270 top
SW4  KT11P3JM  [SW_SMVT_SPST_4]  165.23 106.3 270 top
SW5  KT11P3JM  [SW_SMVT_SPST_4]  174.88 106.3 270 top
SW6  KT11P3JM  [SW_SMVT_SPST_4]  137.16 106.3 270 top
SW7  SLIDE-4P2T  [SW_THVT_4PDT_SLIDE_12]  28.91 9.91 90 top
TP1  HMTSW-101-07-G-S-.240  [HDR_THVT_1X1]  142.37 131.7 0 top
TP2  HMTSW-101-07-G-S-.240  [HDR_THVT_1X1]  142.37 128.14 0 top
TP3  HMTSW-101-07-G-S-.240  [HDR_THVT_1X1]  142.37 124.59 0 top
TP4  HMTSW-101-07-G-S-.240  [HDR_THVT_1X1]  142.37 121.03 0 top
TP5  HMTSW-101-07-G-S-.240  [HDR_THVT_1X1]  151.26 131.7 0 top
TP6  HMTSW-101-07-G-S-.240  [HDR_THVT_1X1]  151.26 128.14 0 top
TP7  HMTSW-101-07-G-S-.240  [HDR_THVT_1X1]  151.26 124.59 0 top
TP8  HMTSW-101-07-G-S-.240  [HDR_THVT_1X1]  151.26 121.03 0 top
TP9  HMTSW-101-07-G-S-.240  [HDR_THVT_1X1]  160.15 131.7 0 top
TP10  HMTSW-101-07-G-S-.240  [HDR_THVT_1X1]  160.15 128.14 0 top
TP11  HMTSW-101-07-G-S-.240  [HDR_THVT_1X1]  160.15 124.59 0 top
TP12  HMTSW-101-07-G-S-.240  [HDR_THVT_1X1]  160.15 121.03 0 top
TP13  HMTSW-101-07-G-S-.240  [HDR_THVT_1X1]  132.97 124.59 0 top
TP14  Testloop_Red  [TP_THVT_060_RND]  23.11 112.14 90 top
TP15  Testloop_White  [TP_THVT_060_RND]  39.12 114.55 90 top
TP16  Testloop_Red  [TP_THVT_060_RND]  22.73 81.79 0 top
TP17  Testloop_Red  [TP_THVT_060_RND]  28.96 131.57 0 top
TP18  Testloop_Red  [TP_THVT_060_RND]  24.13 123.57 0 top
TP19  Testloop_Red  [TP_THVT_060_RND]  47.5 131.57 0 top
TP20  Testloop_Red  [TP_THVT_060_RND]  22.35 58.04 0 top
TP21  Testloop_Red  [TP_THVT_060_RND]  66.04 131.57 0 top
TP22  Testloop_Black  [TP_THVT_060_RND]  24.13 67.31 0 top
TP23  Testloop_Black  [TP_THVT_060_RND]  20.32 103.38 0 top
TP24  Testloop_Black  [TP_THVT_060_RND]  76.58 117.47 0 top
TP25  Testloop_Black  [TP_THVT_060_RND]  2.54 29.84 0 top
TP26  Testloop_Black  [TP_THVT_060_RND]  46.48 115.06 0 top
TP27  Testloop_Black  [TP_THVT_060_RND]  168.53 133.35 0 top
TP28  HMTSW-101-07-G-S-.240  [HDR_THVT_1X1]  132.97 128.14 0 top
TP29  HMTSW-101-07-G-S-.240  [HDR_THVT_1X1]  132.97 131.7 0 top
U1  SN74LVC3G07  [VSSOP_8_83X94_0P5MM]  31.37 18.16 0 top
U2  TPS76933DBVT  [SOT_5_118X67_57]  192.66 140.46 270 top
U3  FT4232H  [LQFP_64_402X402_20]  182.37 124.71 270 top
U4  93LC46B-I/SN  [SOIC-8]  196.72 126.62 270 top
U5  EP4SGX70  [BGA_1152_39]  107.95 76.2 270 top
U6  SN65LVDS1DBVR  [SOP_5_118X67_37]  78.36 107.82 0 top
U7  TPS74401RGW  [QFN_20_203X203_26_PWRPAD]  30.99 113.92 90 top
U8  TPS54620RGY  [QFN_14_144X144_PWRPAD]  5.36 73.91 0 top
U9  TPS54325PWP  [HTSSOP_14_201X177_26_PWRPAD]  35.94 124.84 0 top
U10  TPS54620RGY  [QFN_14_144X144_PWRPAD]  5.36 111.76 0 top
U11  TPS51100DGQ  [SOIC_10_122X122_50_PWRPAD]  37.34 88.52 180 top
U12  TPS54325PWP  [HTSSOP_14_201X177_26_PWRPAD]  73.03 124.84 0 top
U13  TPS54620RGY  [QFN_14_144X144_PWRPAD]  5.36 47.62 0 top
U14  SN74LVC3G07  [VSSOP_8_83X94_0P5MM]  38.35 18.16 0 top
U15  TPS54325PWP  [HTSSOP_14_201X177_26_PWRPAD]  54.48 124.84 0 top
U16  TXB0108PWR  [TSSOP_20_260X177_26]  90.68 134.87 270 top
U17  TXB0108PWR  [TSSOP_20_260X177_26]  183.64 89.66 180 top
U18  TPS74701DRCR  [SON_10_124X124_PWRPAD]  57.66 117.09 180 top
U19  EPCS64  [SOIC_16_410X299_50]  91.44 114.05 270 top
U20  TPS61175  [HTSSOP_14_201X177_26_PWRPAD]  21.08 140.97 0 top
Y1  12MHz w/ 10pF  [XTAL_4_SM_130X102]  187.96 134.62 90 top
Y2  SM5545TEV-100.0MHZ  [OSC-3X5MM]  74.04 111.12 270 top

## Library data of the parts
C1 C5 C13-C19 C49 C51 C53 C59 C61 C64 C65 C75 C82 C84 C86 C87 C97 C99 C338-C342 = CAP0603: tolerance: 10%
C2 C6 C36 C73 C109 = CAP NP_0: tolerance: 10%
C3 C4 C7 C8 C62 C71 C72 C85 C100 = CAP NP: tolerance: 20%
C9 = CAP POL-A: tolerance: 10%
C10 = CAP0402: tolerance: +/-10%
C11 C12 C20 C21 = CAP NP: tolerance: 5%
C22-C34 C37-C39 C41 C45 C94 C95 C101 C103-C108 C110-C116 C118-C123 C125-C138 C140 C141 C143 C156-C162 C164 C165 C179-C255 C257-C293 C337 = CAP
C35 C52 C55 C56 C67 C68 C79 C92 C96 C102 C117 C124 C139 C145-C155 C163 C336 = CAP: tolerance: 20%
C40 = CAPACITOR_NP_1
C46 = CAP_0603
C47 C48 C50 C60 C76 C83 C98 C294 C334 C335 = CAP_0603_H
C54 C66 = CAP POL-E
C57 C58 C63 C69 C70 C74 C90 C91 C93 = CAP0603
C77 = CAP_SMD_POL_1
C78 = CAP_SMD_POL_2
C80 C81 = CAPACITOR_NP_4: tolerance: 10%
C88 = CAP_1210
C144 = CAPT
C166-C178 = CAP_X2Y
C295 = CAP_0603_10uF
C296 = CAP_0603_.027uF
C328-C333 = CAP0201: tolerance: 20%
C349 C350 = CAP_0402_0.1uF
C351-C354 = CAP_0402_10pF
C355 = CAP_0603_4.7pF
CN1 CN4 CN7 CN10 = CA
D1-D10 = LED
D11 = DIODE_SS3P6L
D14 = DIODE ZENER_1
DN1 DN2 = DIODE_DUAL_BAT54CW
F1 F2 = LITTELFUSE_0154007
FB1 FB2 FB4-FB6 = FERRITE_BEAD
J1 = HEADER_2x44_100
J2 = CON_SMVT_60POS_QSH_SAMTEC_0
J3 = CON_SMVT_120POS_QSH_SAMTEC
J4 = CON_SMVT_180POS_QSH_SAMTEC
J5 = USB_MINI_AB_MNE20-5G5P10
J6 = SOCKET-SO-DIMM200
J7 J11 J14-J17 = SMA-THVT_142-0701-201_REC
J8 J10 = CON_THVT_BANANA_JACK_RED
J9 = CON_THVT_BANANA_JACK_BLK
J12 = CONN JACK PWR
J13 = Header_2x5_100_1
J18 = CON_THVT_MOLEX_22-23-2031
JP3 JP4 JP8 = JUMPER_1x3_100
JP5-JP7 = JUMPER_1x2_100
L3 = FERRITE BEAD_0
L4 = BEAD FERRITE/SM_1
L6-L11 = INDUCTOR-1
L12 = IND_0805_H
R1 R2 R4 = R: tolerance: 1%
R3 = R
R5-R8 R20 R23 R31 R39 R45 R46 R77 R79 = RESISTOR
R9 R10 R19 R21 R22 R24-R26 R32 R37 R38 R40 R47-R53 R55 R80-R88 R96-R98 R103 R113-R119 R121-R124 R144 R154 R155 R157 R158 = RES
R15 R16 R54 R56 R76 R104 R105 = RES_0603
R17 R18 = R: tolerance: 5%
R27-R30 R33-R36 R41-R44 R68-R75 = RES0603
R57-R64 R67 R89 R90 R95 R99-R102 R138 R140 R142 = Res_0402_Zero
R65 = R_0: tolerance: 1%
R66 R126-R132 R135 R136 R143 R149-R153 R156 = Res_0402_Zero_H
R91-R94 = res_smd_0
R120 = Res_0603_4.75k
R125 R146 R147 = Res_0603_10k
R133 = Res_0402_100
R134 = Res_0402_24.9_H
R137 R139 R141 = Res_0402_Zero_DNI
R145 = Res_0603_38.3K
R148 = Res_0603_80.6K
RN8 RN9 RN12 RN13 RN18 RN19 RN24 = RA-8P4R
SJP1-SJP3 = JUMPER_SMD_1X3
SW1 = SW-DIP8
SW2-SW6 = SW_SMVT_SPST_4_KT11P3JM
SW7 = SW SLIDE-4P2T_1
TP1-TP13 TP28 TP29 = HEADER_1x1
TP14 TP16-TP21 = TESTLOOP_RED
TP15 = TESTLOOP_WHITE
TP22-TP27 = TP_THVT_060_RND-BLK
U1 U14 = SN74LVC3G07DCU
U2 = TPS769XX-SOT23_0
U3 = FT4232H_2
U4 = EEPROM
U5 = EP4SGX70F1152_2
U6 = SN65LVDS1DBVR
U7 = TPS74401RGW
U8 U10 U13 = TPS54620RGY_0
U9 U12 U15 = TPS54325PWP
U11 = TPS51100DGQ
U16 U17 = TXB0108PWR
U18 = TPS74701DRCR
U19 = EPCS64
U20 = TPS61175
Y1 = CRYSTAL1-4/SM
Y2 = OSC

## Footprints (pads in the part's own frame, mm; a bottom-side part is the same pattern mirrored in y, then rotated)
0201
  rect 0.406x0.406 smd: 1(-0.356,0) 2(0.356,0)
0402
  rect 0.508x0.635 smd: 1(-0.508,0) 2(0.508,0)
0603
  rect 0.762x0.813 smd: 1(-0.787,0) 2(0.787,0)
0805
  rect 1.016x1.27 smd: 1(-1.016,0) 2(1.016,0)
1206
  rect 1.27x1.6 smd: 1(-1.524,0) 2(1.524,0)
1210
  rect 0.965x2.489 smd: 1(-1.372,0) 2(1.372,0)
BGA_1152_39
  round 0.762 smd: (-19,-19) (19,19)
  round 0.483 smd: A2(-15.5,16.5) A3(-14.5,16.5) A4(-13.5,16.5) A5(-12.5,16.5) A6(-11.5,16.5) A7(-10.5,16.5) A8(-9.5,16.5) A9(-8.5,16.5) A10(-7.5,16.5) A11(-6.5,16.5) A12(-5.5,16.5) A13(-4.5,16.5) A14(-3.5,16.5) A15(-2.5,16.5) A16(-1.5,16.5) A17(-0.5,16.5) A18(0.5,16.5) A19(1.5,16.5) A20(2.5,16.5) A21(3.5,16.5) A22(4.5,16.5) A23(5.5,16.5) A24(6.5,16.5) A25(7.5,16.5) A26(8.5,16.5) A27(9.5,16.5) A28(10.5,16.5) A29(11.5,16.5) A30(12.5,16.5) A31(13.5,16.5) A32(14.5,16.5) A33(15.5,16.5) AA1(-16.5,-3.5) AA2(-15.5,-3.5) AA3(-14.5,-3.5) AA4(-13.5,-3.5) AA5(-12.5,-3.5) AA6(-11.5,-3.5) AA7(-10.5,-3.5) AA8(-9.5,-3.5) AA9(-8.5,-3.5) AA10(-7.5,-3.5) AA11(-6.5,-3.5) AA12(-5.5,-3.5) AA13(-4.5,-3.5) AA14(-3.5,-3.5) AA15(-2.5,-3.5) AA16(-1.5,-3.5) AA17(-0.5,-3.5) AA18(0.5,-3.5) AA19(1.5,-3.5) AA20(2.5,-3.5) AA21(3.5,-3.5) AA22(4.5,-3.5) AA23(5.5,-3.5) AA24(6.5,-3.5) AA25(7.5,-3.5) AA26(8.5,-3.5) AA27(9.5,-3.5) AA28(10.5,-3.5) AA29(11.5,-3.5) AA30(12.5,-3.5) AA31(13.5,-3.5) AA32(14.5,-3.5) AA33(15.5,-3.5) AA34(16.5,-3.5) AB1(-16.5,-4.5) AB2(-15.5,-4.5) AB3(-14.5,-4.5) AB4(-13.5,-4.5) AB5(-12.5,-4.5) AB6(-11.5,-4.5) AB7(-10.5,-4.5) AB8(-9.5,-4.5) AB9(-8.5,-4.5) AB10(-7.5,-4.5) AB11(-6.5,-4.5) AB12(-5.5,-4.5) AB13(-4.5,-4.5) AB14(-3.5,-4.5) AB15(-2.5,-4.5) AB16(-1.5,-4.5) AB17(-0.5,-4.5) AB18(0.5,-4.5) AB19(1.5,-4.5) AB20(2.5,-4.5) AB21(3.5,-4.5) AB22(4.5,-4.5) AB23(5.5,-4.5) AB24(6.5,-4.5) AB25(7.5,-4.5) AB26(8.5,-4.5) AB27(9.5,-4.5) AB28(10.5,-4.5) AB29(11.5,-4.5) AB30(12.5,-4.5) AB31(13.5,-4.5) AB32(14.5,-4.5) AB33(15.5,-4.5) AB34(16.5,-4.5) AC1(-16.5,-5.5) AC2(-15.5,-5.5) AC3(-14.5,-5.5) AC4(-13.5,-5.5) AC5(-12.5,-5.5) AC6(-11.5,-5.5) AC7(-10.5,-5.5) AC8(-9.5,-5.5) AC9(-8.5,-5.5) AC10(-7.5,-5.5) AC11(-6.5,-5.5) AC12(-5.5,-5.5) AC13(-4.5,-5.5) AC14(-3.5,-5.5) AC15(-2.5,-5.5) AC16(-1.5,-5.5) AC17(-0.5,-5.5) AC18(0.5,-5.5) AC19(1.5,-5.5) AC20(2.5,-5.5) AC21(3.5,-5.5) AC22(4.5,-5.5) AC23(5.5,-5.5) AC24(6.5,-5.5) AC25(7.5,-5.5) AC26(8.5,-5.5) AC27(9.5,-5.5) AC28(10.5,-5.5) AC29(11.5,-5.5) AC30(12.5,-5.5) AC31(13.5,-5.5) AC32(14.5,-5.5) AC33(15.5,-5.5) AC34(16.5,-5.5) AD1(-16.5,-6.5) AD2(-15.5,-6.5) AD3(-14.5,-6.5) AD4(-13.5,-6.5) AD5(-12.5,-6.5) AD6(-11.5,-6.5) AD7(-10.5,-6.5) AD8(-9.5,-6.5) AD9(-8.5,-6.5) AD10(-7.5,-6.5) AD11(-6.5,-6.5) AD12(-5.5,-6.5) AD13(-4.5,-6.5) AD14(-3.5,-6.5) AD15(-2.5,-6.5) AD16(-1.5,-6.5) AD17(-0.5,-6.5) AD18(0.5,-6.5) AD19(1.5,-6.5) AD20(2.5,-6.5) AD21(3.5,-6.5) AD22(4.5,-6.5) AD23(5.5,-6.5) AD24(6.5,-6.5) AD25(7.5,-6.5) AD26(8.5,-6.5) AD27(9.5,-6.5) AD28(10.5,-6.5) AD29(11.5,-6.5) AD30(12.5,-6.5) AD31(13.5,-6.5) AD32(14.5,-6.5) AD33(15.5,-6.5) AD34(16.5,-6.5) AE1(-16.5,-7.5) AE2(-15.5,-7.5) AE3(-14.5,-7.5) AE4(-13.5,-7.5) AE5(-12.5,-7.5) AE6(-11.5,-7.5) AE7(-10.5,-7.5) AE8(-9.5,-7.5) AE9(-8.5,-7.5) AE10(-7.5,-7.5) AE11(-6.5,-7.5) AE12(-5.5,-7.5) AE13(-4.5,-7.5) AE14(-3.5,-7.5) AE15(-2.5,-7.5) AE16(-1.5,-7.5) AE17(-0.5,-7.5) AE18(0.5,-7.5) AE19(1.5,-7.5) AE20(2.5,-7.5) AE21(3.5,-7.5) AE22(4.5,-7.5) AE23(5.5,-7.5) AE24(6.5,-7.5) AE25(7.5,-7.5) AE26(8.5,-7.5) AE27(9.5,-7.5) AE28(10.5,-7.5) AE29(11.5,-7.5) AE30(12.5,-7.5) AE31(13.5,-7.5) AE32(14.5,-7.5) AE33(15.5,-7.5) AE34(16.5,-7.5) AF1(-16.5,-8.5) AF2(-15.5,-8.5) AF3(-14.5,-8.5) AF4(-13.5,-8.5) AF5(-12.5,-8.5) AF6(-11.5,-8.5) AF7(-10.5,-8.5) AF8(-9.5,-8.5) AF9(-8.5,-8.5) AF10(-7.5,-8.5) AF11(-6.5,-8.5) AF12(-5.5,-8.5) AF13(-4.5,-8.5) AF14(-3.5,-8.5) AF15(-2.5,-8.5) AF16(-1.5,-8.5) AF17(-0.5,-8.5) AF18(0.5,-8.5) AF19(1.5,-8.5) AF20(2.5,-8.5) AF21(3.5,-8.5) AF22(4.5,-8.5) AF23(5.5,-8.5) AF24(6.5,-8.5) AF25(7.5,-8.5) AF26(8.5,-8.5) AF27(9.5,-8.5) AF28(10.5,-8.5) AF29(11.5,-8.5) AF30(12.5,-8.5) AF31(13.5,-8.5) AF32(14.5,-8.5) AF33(15.5,-8.5) AF34(16.5,-8.5) AG1(-16.5,-9.5) AG2(-15.5,-9.5) AG3(-14.5,-9.5) AG4(-13.5,-9.5) AG5(-12.5,-9.5) AG6(-11.5,-9.5) AG7(-10.5,-9.5) AG8(-9.5,-9.5) AG9(-8.5,-9.5) AG10(-7.5,-9.5) AG11(-6.5,-9.5) AG12(-5.5,-9.5) AG13(-4.5,-9.5) AG14(-3.5,-9.5) AG15(-2.5,-9.5) AG16(-1.5,-9.5) AG17(-0.5,-9.5) AG18(0.5,-9.5) AG19(1.5,-9.5) AG20(2.5,-9.5) AG21(3.5,-9.5) AG22(4.5,-9.5) AG23(5.5,-9.5) AG24(6.5,-9.5) AG25(7.5,-9.5) AG26(8.5,-9.5) AG27(9.5,-9.5) AG28(10.5,-9.5) AG29(11.5,-9.5) AG30(12.5,-9.5) AG31(13.5,-9.5) AG32(14.5,-9.5) AG33(15.5,-9.5) AG34(16.5,-9.5) AH1(-16.5,-10.5) AH2(-15.5,-10.5) AH3(-14.5,-10.5) AH4(-13.5,-10.5) AH5(-12.5,-10.5) AH6(-11.5,-10.5) AH7(-10.5,-10.5) AH8(-9.5,-10.5) AH9(-8.5,-10.5) AH10(-7.5,-10.5) AH11(-6.5,-10.5) AH12(-5.5,-10.5) AH13(-4.5,-10.5) AH14(-3.5,-10.5) AH15(-2.5,-10.5) AH16(-1.5,-10.5) AH17(-0.5,-10.5) AH18(0.5,-10.5) AH19(1.5,-10.5) AH20(2.5,-10.5) AH21(3.5,-10.5) AH22(4.5,-10.5) AH23(5.5,-10.5) AH24(6.5,-10.5) AH25(7.5,-10.5) AH26(8.5,-10.5) AH27(9.5,-10.5) AH28(10.5,-10.5) AH29(11.5,-10.5) AH30(12.5,-10.5) AH31(13.5,-10.5) AH32(14.5,-10.5) AH33(15.5,-10.5) AH34(16.5,-10.5) AJ1(-16.5,-11.5) AJ2(-15.5,-11.5) AJ3(-14.5,-11.5) AJ4(-13.5,-11.5) AJ5(-12.5,-11.5) AJ6(-11.5,-11.5) AJ7(-10.5,-11.5) AJ8(-9.5,-11.5) AJ9(-8.5,-11.5) AJ10(-7.5,-11.5) AJ11(-6.5,-11.5) AJ12(-5.5,-11.5) AJ13(-4.5,-11.5) AJ14(-3.5,-11.5) AJ15(-2.5,-11.5) AJ16(-1.5,-11.5) AJ17(-0.5,-11.5) AJ18(0.5,-11.5) AJ19(1.5,-11.5) AJ20(2.5,-11.5) AJ21(3.5,-11.5) AJ22(4.5,-11.5) AJ23(5.5,-11.5) AJ24(6.5,-11.5) AJ25(7.5,-11.5) AJ26(8.5,-11.5) AJ27(9.5,-11.5) AJ28(10.5,-11.5) AJ29(11.5,-11.5) AJ30(12.5,-11.5) AJ31(13.5,-11.5) AJ32(14.5,-11.5) AJ33(15.5,-11.5) AJ34(16.5,-11.5) AK1(-16.5,-12.5) AK2(-15.5,-12.5) AK3(-14.5,-12.5) AK4(-13.5,-12.5) AK5(-12.5,-12.5) AK6(-11.5,-12.5) AK7(-10.5,-12.5) AK8(-9.5,-12.5) AK9(-8.5,-12.5) AK10(-7.5,-12.5) AK11(-6.5,-12.5) AK12(-5.5,-12.5) AK13(-4.5,-12.5) AK14(-3.5,-12.5) AK15(-2.5,-12.5) AK16(-1.5,-12.5) AK17(-0.5,-12.5) AK18(0.5,-12.5) AK19(1.5,-12.5) AK20(2.5,-12.5) AK21(3.5,-12.5) AK22(4.5,-12.5) AK23(5.5,-12.5) AK24(6.5,-12.5) AK25(7.5,-12.5) AK26(8.5,-12.5) AK27(9.5,-12.5) AK28(10.5,-12.5) AK29(11.5,-12.5) AK30(12.5,-12.5) AK31(13.5,-12.5) AK32(14.5,-12.5) AK33(15.5,-12.5) AK34(16.5,-12.5) AL1(-16.5,-13.5) AL2(-15.5,-13.5) AL3(-14.5,-13.5) AL4(-13.5,-13.5) AL5(-12.5,-13.5) AL6(-11.5,-13.5) AL7(-10.5,-13.5) AL8(-9.5,-13.5) AL9(-8.5,-13.5) AL10(-7.5,-13.5) AL11(-6.5,-13.5) AL12(-5.5,-13.5) AL13(-4.5,-13.5) AL14(-3.5,-13.5) AL15(-2.5,-13.5) AL16(-1.5,-13.5) AL17(-0.5,-13.5) AL18(0.5,-13.5) AL19(1.5,-13.5) AL20(2.5,-13.5) AL21(3.5,-13.5) AL22(4.5,-13.5) AL23(5.5,-13.5) AL24(6.5,-13.5) AL25(7.5,-13.5) AL26(8.5,-13.5) AL27(9.5,-13.5) AL28(10.5,-13.5) AL29(11.5,-13.5) AL30(12.5,-13.5) AL31(13.5,-13.5) AL32(14.5,-13.5) AL33(15.5,-13.5) AL34(16.5,-13.5) AM1(-16.5,-14.5) AM2(-15.5,-14.5) AM3(-14.5,-14.5) AM4(-13.5,-14.5) AM5(-12.5,-14.5) AM6(-11.5,-14.5) AM7(-10.5,-14.5) AM8(-9.5,-14.5) AM9(-8.5,-14.5) AM10(-7.5,-14.5) AM11(-6.5,-14.5) AM12(-5.5,-14.5) AM13(-4.5,-14.5) AM14(-3.5,-14.5) AM15(-2.5,-14.5) AM16(-1.5,-14.5) AM17(-0.5,-14.5) AM18(0.5,-14.5) AM19(1.5,-14.5) AM20(2.5,-14.5) AM21(3.5,-14.5) AM22(4.5,-14.5) AM23(5.5,-14.5) AM24(6.5,-14.5) AM25(7.5,-14.5) AM26(8.5,-14.5) AM27(9.5,-14.5) AM28(10.5,-14.5) AM29(11.5,-14.5) AM30(12.5,-14.5) AM31(13.5,-14.5) AM32(14.5,-14.5) AM33(15.5,-14.5) AM34(16.5,-14.5) AN1(-16.5,-15.5) AN2(-15.5,-15.5) AN3(-14.5,-15.5) AN4(-13.5,-15.5) AN5(-12.5,-15.5) AN6(-11.5,-15.5) AN7(-10.5,-15.5) AN8(-9.5,-15.5) AN9(-8.5,-15.5) AN10(-7.5,-15.5) AN11(-6.5,-15.5) AN12(-5.5,-15.5) AN13(-4.5,-15.5) AN14(-3.5,-15.5) AN15(-2.5,-15.5) AN16(-1.5,-15.5) AN17(-0.5,-15.5) AN18(0.5,-15.5) AN19(1.5,-15.5) AN20(2.5,-15.5) AN21(3.5,-15.5) AN22(4.5,-15.5) AN23(5.5,-15.5) AN24(6.5,-15.5) AN25(7.5,-15.5) AN26(8.5,-15.5) AN27(9.5,-15.5) AN28(10.5,-15.5) AN29(11.5,-15.5) AN30(12.5,-15.5) AN31(13.5,-15.5) AN32(14.5,-15.5) AN33(15.5,-15.5) AN34(16.5,-15.5) AP2(-15.5,-16.5) AP3(-14.5,-16.5) AP4(-13.5,-16.5) AP5(-12.5,-16.5) AP6(-11.5,-16.5) AP7(-10.5,-16.5) AP8(-9.5,-16.5) AP9(-8.5,-16.5) AP10(-7.5,-16.5) AP11(-6.5,-16.5) AP12(-5.5,-16.5) AP13(-4.5,-16.5) AP14(-3.5,-16.5) AP15(-2.5,-16.5) AP16(-1.5,-16.5) AP17(-0.5,-16.5) AP18(0.5,-16.5) AP19(1.5,-16.5) AP20(2.5,-16.5) AP21(3.5,-16.5) AP22(4.5,-16.5) AP23(5.5,-16.5) AP24(6.5,-16.5) AP25(7.5,-16.5) AP26(8.5,-16.5) AP27(9.5,-16.5) AP28(10.5,-16.5) AP29(11.5,-16.5) AP30(12.5,-16.5) AP31(13.5,-16.5) AP32(14.5,-16.5) AP33(15.5,-16.5) B1(-16.5,15.5) B2(-15.5,15.5) B3(-14.5,15.5) B4(-13.5,15.5) B5(-12.5,15.5) B6(-11.5,15.5) B7(-10.5,15.5) B8(-9.5,15.5) B9(-8.5,15.5) B10(-7.5,15.5) B11(-6.5,15.5) B12(-5.5,15.5) B13(-4.5,15.5) B14(-3.5,15.5) B15(-2.5,15.5) B16(-1.5,15.5) B17(-0.5,15.5) B18(0.5,15.5) B19(1.5,15.5) B20(2.5,15.5) B21(3.5,15.5) B22(4.5,15.5) B23(5.5,15.5) B24(6.5,15.5) B25(7.5,15.5) B26(8.5,15.5) B27(9.5,15.5) B28(10.5,15.5) B29(11.5,15.5) B30(12.5,15.5) B31(13.5,15.5) B32(14.5,15.5) B33(15.5,15.5) B34(16.5,15.5) C1(-16.5,14.5) C2(-15.5,14.5) C3(-14.5,14.5) C4(-13.5,14.5) C5(-12.5,14.5) C6(-11.5,14.5) C7(-10.5,14.5) C8(-9.5,14.5) C9(-8.5,14.5) C10(-7.5,14.5) C11(-6.5,14.5) C12(-5.5,14.5) C13(-4.5,14.5) C14(-3.5,14.5) C15(-2.5,14.5) C16(-1.5,14.5) C17(-0.5,14.5) C18(0.5,14.5) C19(1.5,14.5) C20(2.5,14.5) C21(3.5,14.5) C22(4.5,14.5) C23(5.5,14.5) C24(6.5,14.5) C25(7.5,14.5) C26(8.5,14.5) C27(9.5,14.5) C28(10.5,14.5) C29(11.5,14.5) C30(12.5,14.5) C31(13.5,14.5) C32(14.5,14.5) C33(15.5,14.5) C34(16.5,14.5) D1(-16.5,13.5) D2(-15.5,13.5) D3(-14.5,13.5) D4(-13.5,13.5) D5(-12.5,13.5) D6(-11.5,13.5) D7(-10.5,13.5) D8(-9.5,13.5) D9(-8.5,13.5) D10(-7.5,13.5) D11(-6.5,13.5) D12(-5.5,13.5) D13(-4.5,13.5) D14(-3.5,13.5) D15(-2.5,13.5) D16(-1.5,13.5) D17(-0.5,13.5) D18(0.5,13.5) D19(1.5,13.5) D20(2.5,13.5) D21(3.5,13.5) D22(4.5,13.5) D23(5.5,13.5) D24(6.5,13.5) D25(7.5,13.5) D26(8.5,13.5) D27(9.5,13.5) D28(10.5,13.5) D29(11.5,13.5) D30(12.5,13.5) D31(13.5,13.5) D32(14.5,13.5) D33(15.5,13.5) D34(16.5,13.5) E1(-16.5,12.5) E2(-15.5,12.5) E3(-14.5,12.5) E4(-13.5,12.5) E5(-12.5,12.5) E6(-11.5,12.5) E7(-10.5,12.5) E8(-9.5,12.5) E9(-8.5,12.5) E10(-7.5,12.5) E11(-6.5,12.5) E12(-5.5,12.5) E13(-4.5,12.5) E14(-3.5,12.5) E15(-2.5,12.5) E16(-1.5,12.5) E17(-0.5,12.5) E18(0.5,12.5) E19(1.5,12.5) E20(2.5,12.5) E21(3.5,12.5) E22(4.5,12.5) E23(5.5,12.5) E24(6.5,12.5) E25(7.5,12.5) E26(8.5,12.5) E27(9.5,12.5) E28(10.5,12.5) E29(11.5,12.5) E30(12.5,12.5) E31(13.5,12.5) E32(14.5,12.5) E33(15.5,12.5) E34(16.5,12.5) F1(-16.5,11.5) F2(-15.5,11.5) F3(-14.5,11.5) F4(-13.5,11.5) F5(-12.5,11.5) F6(-11.5,11.5) F7(-10.5,11.5) F8(-9.5,11.5) F9(-8.5,11.5) F10(-7.5,11.5) F11(-6.5,11.5) F12(-5.5,11.5) F13(-4.5,11.5) F14(-3.5,11.5) F15(-2.5,11.5) F16(-1.5,11.5) F17(-0.5,11.5) F18(0.5,11.5) F19(1.5,11.5) F20(2.5,11.5) F21(3.5,11.5) F22(4.5,11.5) F23(5.5,11.5) F24(6.5,11.5) F25(7.5,11.5) F26(8.5,11.5) F27(9.5,11.5) F28(10.5,11.5) F29(11.5,11.5) F30(12.5,11.5) F31(13.5,11.5) F32(14.5,11.5) F33(15.5,11.5) F34(16.5,11.5) G1(-16.5,10.5) G2(-15.5,10.5) G3(-14.5,10.5) G4(-13.5,10.5) G5(-12.5,10.5) G6(-11.5,10.5) G7(-10.5,10.5) G8(-9.5,10.5) G9(-8.5,10.5) G10(-7.5,10.5) G11(-6.5,10.5) G12(-5.5,10.5) G13(-4.5,10.5) G14(-3.5,10.5) G15(-2.5,10.5) G16(-1.5,10.5) G17(-0.5,10.5) G18(0.5,10.5) G19(1.5,10.5) G20(2.5,10.5) G21(3.5,10.5) G22(4.5,10.5) G23(5.5,10.5) G24(6.5,10.5) G25(7.5,10.5) G26(8.5,10.5) G27(9.5,10.5) G28(10.5,10.5) G29(11.5,10.5) G30(12.5,10.5) G31(13.5,10.5) G32(14.5,10.5) G33(15.5,10.5) G34(16.5,10.5) H1(-16.5,9.5) H2(-15.5,9.5) H3(-14.5,9.5) H4(-13.5,9.5) H5(-12.5,9.5) H6(-11.5,9.5) H7(-10.5,9.5) H8(-9.5,9.5) H9(-8.5,9.5) H10(-7.5,9.5) H11(-6.5,9.5) H12(-5.5,9.5) H13(-4.5,9.5) H14(-3.5,9.5) H15(-2.5,9.5) H16(-1.5,9.5) H17(-0.5,9.5) H18(0.5,9.5) H19(1.5,9.5) H20(2.5,9.5) H21(3.5,9.5) H22(4.5,9.5) H23(5.5,9.5) H24(6.5,9.5) H25(7.5,9.5) H26(8.5,9.5) H27(9.5,9.5) H28(10.5,9.5) H29(11.5,9.5) H30(12.5,9.5) H31(13.5,9.5) H32(14.5,9.5) H33(15.5,9.5) H34(16.5,9.5) J1(-16.5,8.5) J2(-15.5,8.5) J3(-14.5,8.5) J4(-13.5,8.5) J5(-12.5,8.5) J6(-11.5,8.5) J7(-10.5,8.5) J8(-9.5,8.5) J9(-8.5,8.5) J10(-7.5,8.5) J11(-6.5,8.5) J12(-5.5,8.5) J13(-4.5,8.5) J14(-3.5,8.5) J15(-2.5,8.5) J16(-1.5,8.5) J17(-0.5,8.5) J18(0.5,8.5) J19(1.5,8.5) J20(2.5,8.5) J21(3.5,8.5) J22(4.5,8.5) J23(5.5,8.5) J24(6.5,8.5) J25(7.5,8.5) J26(8.5,8.5) J27(9.5,8.5) J28(10.5,8.5) J29(11.5,8.5) J30(12.5,8.5) J31(13.5,8.5) J32(14.5,8.5) J33(15.5,8.5) J34(16.5,8.5) K1(-16.5,7.5) K2(-15.5,7.5) K3(-14.5,7.5) K4(-13.5,7.5) K5(-12.5,7.5) K6(-11.5,7.5) K7(-10.5,7.5) K8(-9.5,7.5) K9(-8.5,7.5) K10(-7.5,7.5) K11(-6.5,7.5) K12(-5.5,7.5) K13(-4.5,7.5) K14(-3.5,7.5) K15(-2.5,7.5) K16(-1.5,7.5) K17(-0.5,7.5) K18(0.5,7.5) K19(1.5,7.5) K20(2.5,7.5) K21(3.5,7.5) K22(4.5,7.5) K23(5.5,7.5) K24(6.5,7.5) K25(7.5,7.5) K26(8.5,7.5) K27(9.5,7.5) K28(10.5,7.5) K29(11.5,7.5) K30(12.5,7.5) K31(13.5,7.5) K32(14.5,7.5) K33(15.5,7.5) K34(16.5,7.5) L1(-16.5,6.5) L2(-15.5,6.5) L3(-14.5,6.5) L4(-13.5,6.5) L5(-12.5,6.5) L6(-11.5,6.5) L7(-10.5,6.5) L8(-9.5,6.5) L9(-8.5,6.5) L10(-7.5,6.5) L11(-6.5,6.5) L12(-5.5,6.5) L13(-4.5,6.5) L14(-3.5,6.5) L15(-2.5,6.5) L16(-1.5,6.5) L17(-0.5,6.5) L18(0.5,6.5) L19(1.5,6.5) L20(2.5,6.5) L21(3.5,6.5) L22(4.5,6.5) L23(5.5,6.5) L24(6.5,6.5) L25(7.5,6.5) L26(8.5,6.5) L27(9.5,6.5) L28(10.5,6.5) L29(11.5,6.5) L30(12.5,6.5) L31(13.5,6.5) L32(14.5,6.5) L33(15.5,6.5) L34(16.5,6.5) M1(-16.5,5.5) M2(-15.5,5.5) M3(-14.5,5.5) M4(-13.5,5.5) M5(-12.5,5.5) M6(-11.5,5.5) M7(-10.5,5.5) M8(-9.5,5.5) M9(-8.5,5.5) M10(-7.5,5.5) M11(-6.5,5.5) M12(-5.5,5.5) M13(-4.5,5.5) M14(-3.5,5.5) M15(-2.5,5.5) M16(-1.5,5.5) M17(-0.5,5.5) M18(0.5,5.5) M19(1.5,5.5) M20(2.5,5.5) M21(3.5,5.5) M22(4.5,5.5) M23(5.5,5.5) M24(6.5,5.5) M25(7.5,5.5) M26(8.5,5.5) M27(9.5,5.5) M28(10.5,5.5) M29(11.5,5.5) M30(12.5,5.5) M31(13.5,5.5) M32(14.5,5.5) M33(15.5,5.5) M34(16.5,5.5) N1(-16.5,4.5) N2(-15.5,4.5) N3(-14.5,4.5) N4(-13.5,4.5) N5(-12.5,4.5) N6(-11.5,4.5) N7(-10.5,4.5) N8(-9.5,4.5) N9(-8.5,4.5) N10(-7.5,4.5) N11(-6.5,4.5) N12(-5.5,4.5) N13(-4.5,4.5) N14(-3.5,4.5) N15(-2.5,4.5) N16(-1.5,4.5) N17(-0.5,4.5) N18(0.5,4.5) N19(1.5,4.5) N20(2.5,4.5) N21(3.5,4.5) N22(4.5,4.5) N23(5.5,4.5) N24(6.5,4.5) N25(7.5,4.5) N26(8.5,4.5) N27(9.5,4.5) N28(10.5,4.5) N29(11.5,4.5) N30(12.5,4.5) N31(13.5,4.5) N32(14.5,4.5) N33(15.5,4.5) N34(16.5,4.5) P1(-16.5,3.5) P2(-15.5,3.5) P3(-14.5,3.5) P4(-13.5,3.5) P5(-12.5,3.5) P6(-11.5,3.5) P7(-10.5,3.5) P8(-9.5,3.5) P9(-8.5,3.5) P10(-7.5,3.5) P11(-6.5,3.5) P12(-5.5,3.5) P13(-4.5,3.5) P14(-3.5,3.5) P15(-2.5,3.5) P16(-1.5,3.5) P17(-0.5,3.5) P18(0.5,3.5) P19(1.5,3.5) P20(2.5,3.5) P21(3.5,3.5) P22(4.5,3.5) P23(5.5,3.5) P24(6.5,3.5) P25(7.5,3.5) P26(8.5,3.5) P27(9.5,3.5) P28(10.5,3.5) P29(11.5,3.5) P30(12.5,3.5) P31(13.5,3.5) P32(14.5,3.5) P33(15.5,3.5) P34(16.5,3.5) R1(-16.5,2.5) R2(-15.5,2.5) R3(-14.5,2.5) R4(-13.5,2.5) R5(-12.5,2.5) R6(-11.5,2.5) R7(-10.5,2.5) R8(-9.5,2.5) R9(-8.5,2.5) R10(-7.5,2.5) R11(-6.5,2.5) R12(-5.5,2.5) R13(-4.5,2.5) R14(-3.5,2.5) R15(-2.5,2.5) R16(-1.5,2.5) R17(-0.5,2.5) R18(0.5,2.5) R19(1.5,2.5) R20(2.5,2.5) R21(3.5,2.5) R22(4.5,2.5) R23(5.5,2.5) R24(6.5,2.5) R25(7.5,2.5) R26(8.5,2.5) R27(9.5,2.5) R28(10.5,2.5) R29(11.5,2.5) R30(12.5,2.5) R31(13.5,2.5) R32(14.5,2.5) R33(15.5,2.5) R34(16.5,2.5) T1(-16.5,1.5) T2(-15.5,1.5) T3(-14.5,1.5) T4(-13.5,1.5) T5(-12.5,1.5) T6(-11.5,1.5) T7(-10.5,1.5) T8(-9.5,1.5) T9(-8.5,1.5) T10(-7.5,1.5) T11(-6.5,1.5) T12(-5.5,1.5) T13(-4.5,1.5) T14(-3.5,1.5) T15(-2.5,1.5) T16(-1.5,1.5) T17(-0.5,1.5) T18(0.5,1.5) T19(1.5,1.5) T20(2.5,1.5) T21(3.5,1.5) T22(4.5,1.5) T23(5.5,1.5) T24(6.5,1.5) T25(7.5,1.5) T26(8.5,1.5) T27(9.5,1.5) T28(10.5,1.5) T29(11.5,1.5) T30(12.5,1.5) T31(13.5,1.5) T32(14.5,1.5) T33(15.5,1.5) T34(16.5,1.5) U1(-16.5,0.5) U2(-15.5,0.5) U3(-14.5,0.5) U4(-13.5,0.5) U5(-12.5,0.5) U6(-11.5,0.5) U7(-10.5,0.5) U8(-9.5,0.5) U9(-8.5,0.5) U10(-7.5,0.5) U11(-6.5,0.5) U12(-5.5,0.5) U13(-4.5,0.5) U14(-3.5,0.5) U15(-2.5,0.5) U16(-1.5,0.5) U17(-0.5,0.5) U18(0.5,0.5) U19(1.5,0.5) U20(2.5,0.5) U21(3.5,0.5) U22(4.5,0.5) U23(5.5,0.5) U24(6.5,0.5) U25(7.5,0.5) U26(8.5,0.5) U27(9.5,0.5) U28(10.5,0.5) U29(11.5,0.5) U30(12.5,0.5) U31(13.5,0.5) U32(14.5,0.5) U33(15.5,0.5) U34(16.5,0.5) V1(-16.5,-0.5) V2(-15.5,-0.5) V3(-14.5,-0.5) V4(-13.5,-0.5) V5(-12.5,-0.5) V6(-11.5,-0.5) V7(-10.5,-0.5) V8(-9.5,-0.5) V9(-8.5,-0.5) V10(-7.5,-0.5) V11(-6.5,-0.5) V12(-5.5,-0.5) V13(-4.5,-0.5) V14(-3.5,-0.5) V15(-2.5,-0.5) V16(-1.5,-0.5) V17(-0.5,-0.5) V18(0.5,-0.5) V19(1.5,-0.5) V20(2.5,-0.5) V21(3.5,-0.5) V22(4.5,-0.5) V23(5.5,-0.5) V24(6.5,-0.5) V25(7.5,-0.5) V26(8.5,-0.5) V27(9.5,-0.5) V28(10.5,-0.5) V29(11.5,-0.5) V30(12.5,-0.5) V31(13.5,-0.5) V32(14.5,-0.5) V33(15.5,-0.5) V34(16.5,-0.5) W1(-16.5,-1.5) W2(-15.5,-1.5) W3(-14.5,-1.5) W4(-13.5,-1.5) W5(-12.5,-1.5) W6(-11.5,-1.5) W7(-10.5,-1.5) W8(-9.5,-1.5) W9(-8.5,-1.5) W10(-7.5,-1.5) W11(-6.5,-1.5) W12(-5.5,-1.5) W13(-4.5,-1.5) W14(-3.5,-1.5) W15(-2.5,-1.5) W16(-1.5,-1.5) W17(-0.5,-1.5) W18(0.5,-1.5) W19(1.5,-1.5) W20(2.5,-1.5) W21(3.5,-1.5) W22(4.5,-1.5) W23(5.5,-1.5) W24(6.5,-1.5) W25(7.5,-1.5) W26(8.5,-1.5) W27(9.5,-1.5) W28(10.5,-1.5) W29(11.5,-1.5) W30(12.5,-1.5) W31(13.5,-1.5) W32(14.5,-1.5) W33(15.5,-1.5) W34(16.5,-1.5) Y1(-16.5,-2.5) Y2(-15.5,-2.5) Y3(-14.5,-2.5) Y4(-13.5,-2.5) Y5(-12.5,-2.5) Y6(-11.5,-2.5) Y7(-10.5,-2.5) Y8(-9.5,-2.5) Y9(-8.5,-2.5) Y10(-7.5,-2.5) Y11(-6.5,-2.5) Y12(-5.5,-2.5) Y13(-4.5,-2.5) Y14(-3.5,-2.5) Y15(-2.5,-2.5) Y16(-1.5,-2.5) Y17(-0.5,-2.5) Y18(0.5,-2.5) Y19(1.5,-2.5) Y20(2.5,-2.5) Y21(3.5,-2.5) Y22(4.5,-2.5) Y23(5.5,-2.5) Y24(6.5,-2.5) Y25(7.5,-2.5) Y26(8.5,-2.5) Y27(9.5,-2.5) Y28(10.5,-2.5) Y29(11.5,-2.5) Y30(12.5,-2.5) Y31(13.5,-2.5) Y32(14.5,-2.5) Y33(15.5,-2.5) Y34(16.5,-2.5)
